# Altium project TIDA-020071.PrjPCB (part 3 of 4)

## Sheet Connector.SchDoc
size A3; Date: Not shown in title block; ApprovedBy: Not shown in title block; CheckedBy: Not shown in title block; Author: Not shown in title block; CompanyName: Not shown in title block; Engineer: Not shown in title block; Organization: Not shown in title block; Address1: Not shown in title block; Address2: Not shown in title block; Address3: Not shown in title block; Address4: Not shown in title block; DocumentNumber: 1; Revision: Use project parameter SCH_Rev; SheetNumber: 1; SheetTotal: 15; PageSetup: Record=PageOptions¦CenterHorizontal=True¦CenterVertical=True¦PrintScale=1.00¦XCorrection=1.00¦YCorrection=1.00¦PrintKind=0¦BorderSize=5000000¦LeftOffset=0¦BottomOffset=0¦Orientation=2¦PaperLength=1000¦PaperWidth=1000¦Scale=100¦PaperSource=15¦PrintQuality=600¦MediaType=1¦DitherType=10¦PaperKind=Letter¦PrintScaleMode=1
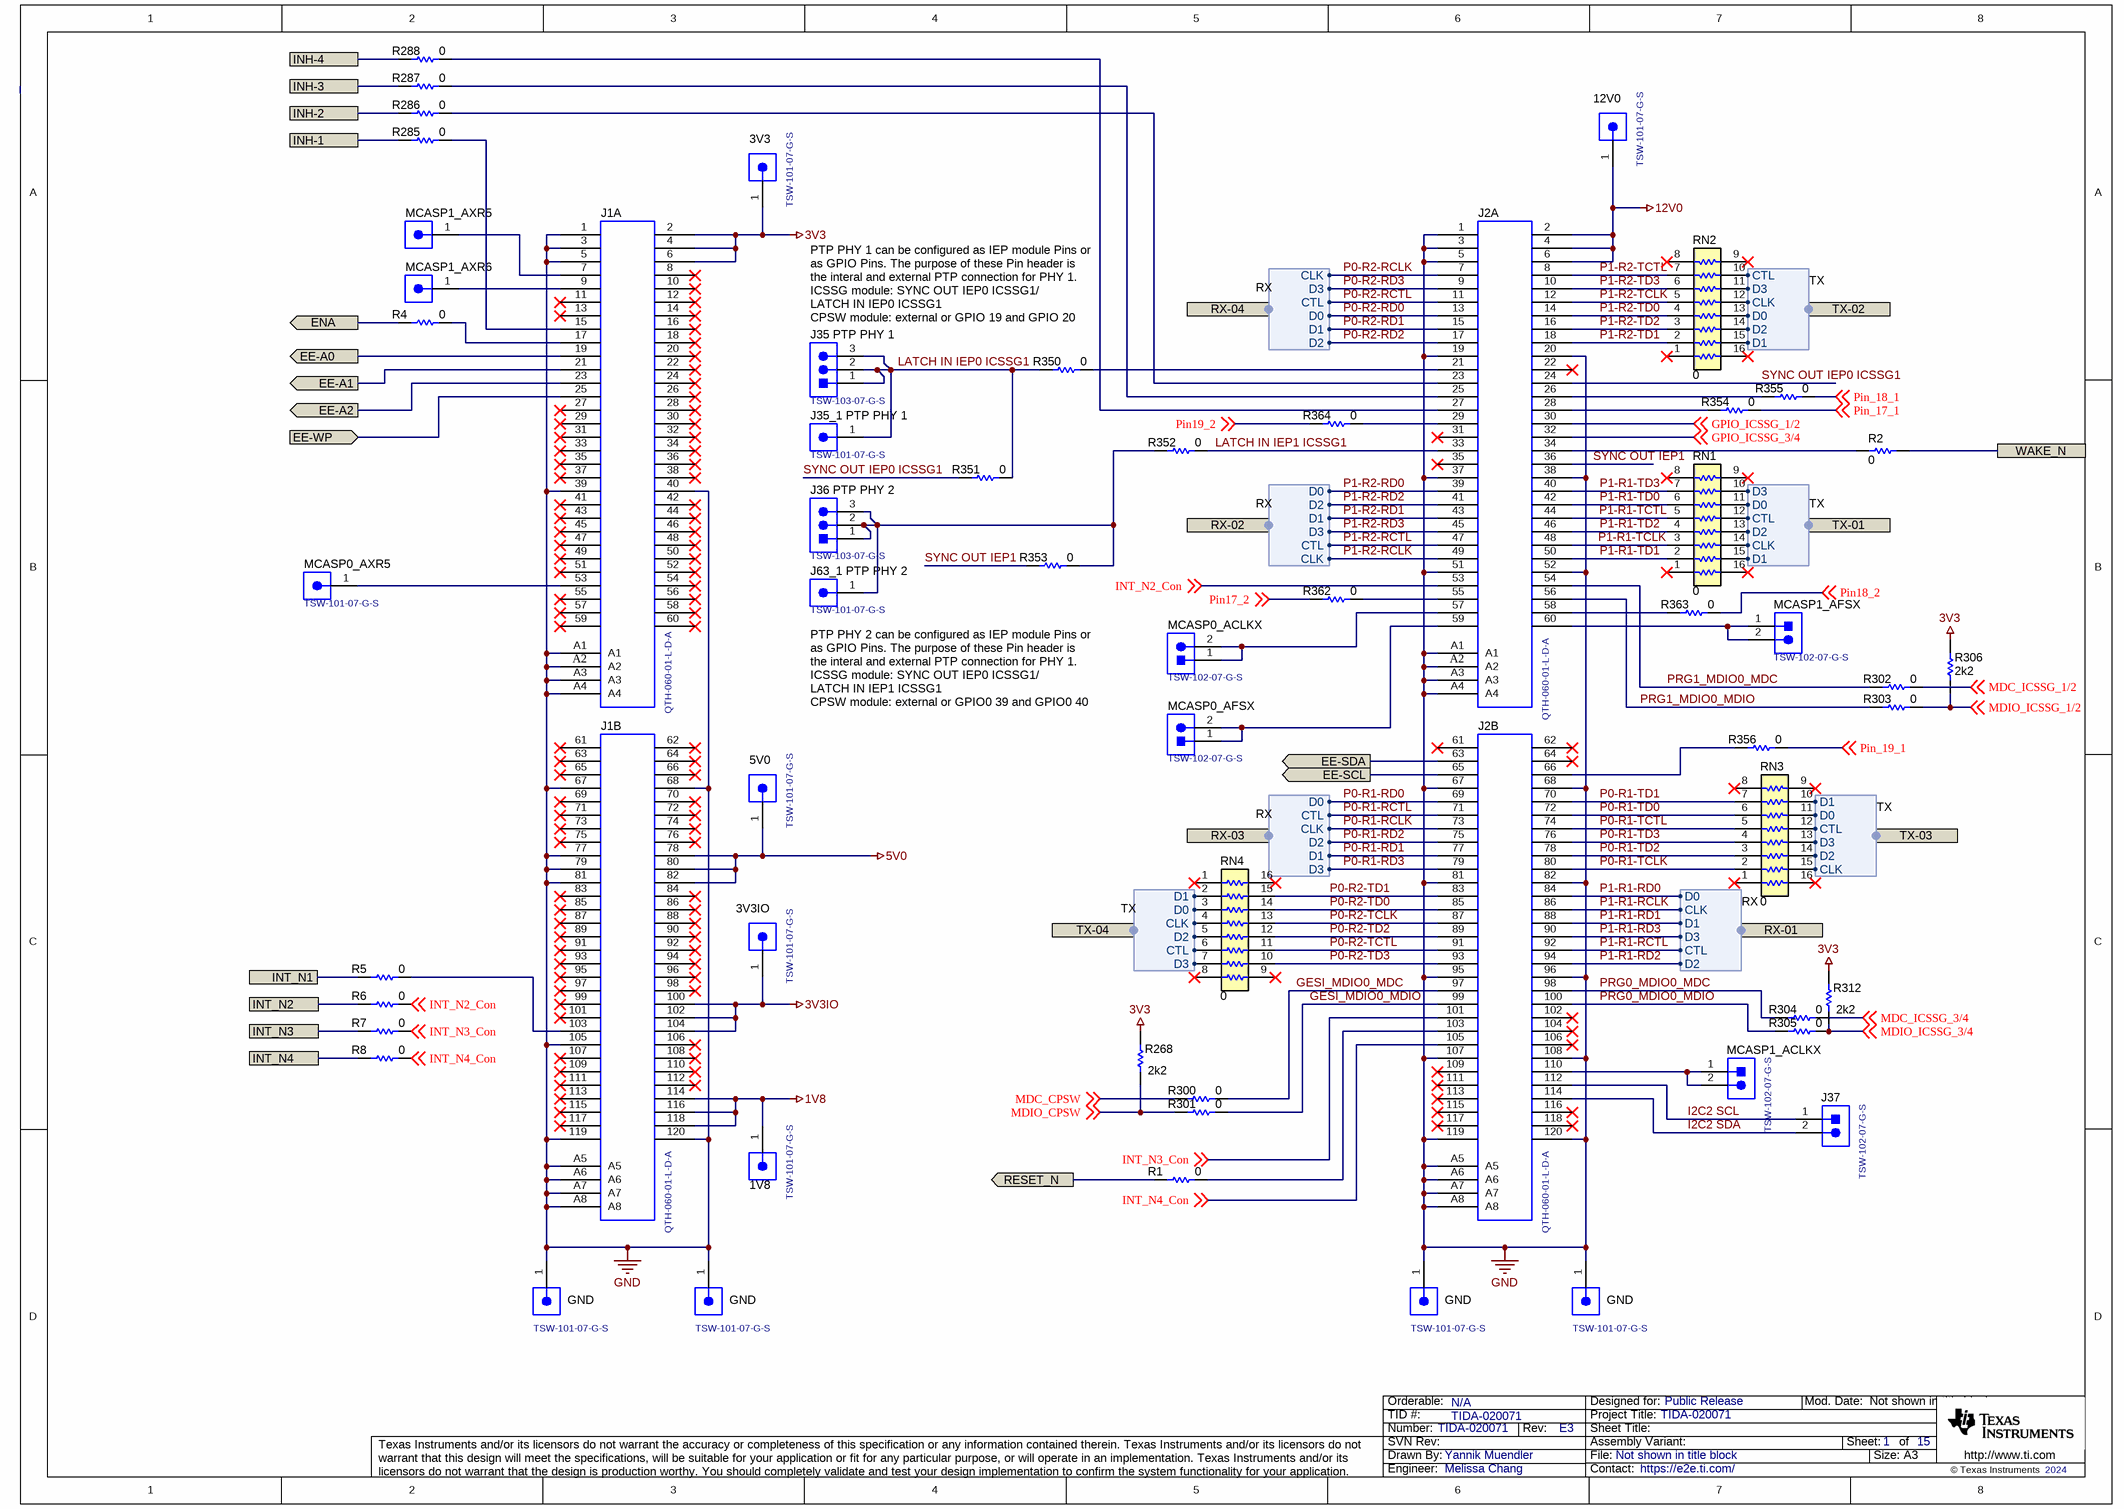
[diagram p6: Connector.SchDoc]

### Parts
(Parts that share a designator on the sheet are numbered #1, #2 ... from top to bottom, then left to right.)
1V8  TSW-101-07-G-S  [TSW-101-07-G-S]
3V3  TSW-101-07-G-S  [TSW-101-07-G-S]
3V3IO  TSW-101-07-G-S  [TSW-101-07-G-S]
5V0  TSW-101-07-G-S  [TSW-101-07-G-S]
12V0  TSW-101-07-G-S  [TSW-101-07-G-S]
GND#1  TSW-101-07-G-S  [TSW-101-07-G-S]
GND#2  TSW-101-07-G-S  [TSW-101-07-G-S]
GND#3  TSW-101-07-G-S  [TSW-101-07-G-S]
GND#4  TSW-101-07-G-S  [TSW-101-07-G-S]
J1  QTH-060-01-L-D-A  [SAMTEC_QTH-060-01-L-D-A]  (parts A,B of 2)
J2  QTH-060-01-L-D-A  [SAMTEC_QTH-060-01-L-D-A]  (parts A,B of 2)
J35_1_PTP_PHY_1  TSW-101-07-G-S  [TSW-101-07-G-S]
J35_PTP_PHY_1  TSW-103-07-G-S  [TSW-103-07-G-S]
J36_PTP_PHY_2  TSW-103-07-G-S  [TSW-103-07-G-S]
J37  TSW-102-07-G-S  [TSW-102-07-G-S]
J63_1_PTP_PHY_2  TSW-101-07-G-S  [TSW-101-07-G-S]
MCASP0_ACLKX  TSW-102-07-G-S  [TSW-102-07-G-S]
MCASP0_AFSX  TSW-102-07-G-S  [TSW-102-07-G-S]
MCASP0_AXR5  TSW-101-07-G-S  [TSW-101-07-G-S]
MCASP1_ACLKX  TSW-102-07-G-S  [TSW-102-07-G-S]
MCASP1_AFSX  TSW-102-07-G-S  [TSW-102-07-G-S]
MCASP1_AXR5  TSW-101-07-G-S  [TSW-101-07-G-S]  (value not drawn)
MCASP1_AXR6  TSW-101-07-G-S  [TSW-101-07-G-S]  (value not drawn)
R1  ValueDisplayed: 0  [0402]  (hidden comment: CRCW04020000Z0EDHP)
R2  ValueDisplayed: 0  [0402]  (hidden comment: CRCW04020000Z0EDHP)
R4  ValueDisplayed: 0  [0402]  (hidden comment: CRCW04020000Z0EDHP)
R5  ValueDisplayed: 0  [0402]  (hidden comment: CRCW04020000Z0EDHP)
R6  ValueDisplayed: 0  [0402]  (hidden comment: CRCW04020000Z0EDHP)
R7  ValueDisplayed: 0  [0402]  (hidden comment: CRCW04020000Z0EDHP)
R8  ValueDisplayed: 0  [0402]  (hidden comment: CRCW04020000Z0EDHP)
R268  ValueDisplayed: 2k2  [0402]  (hidden comment: CRCW04022K20JNED)
R285  ValueDisplayed: 0  [0402]  (hidden comment: CRCW04020000Z0EDHP)
R286  ValueDisplayed: 0  [0402]  (hidden comment: CRCW04020000Z0EDHP)
R287  ValueDisplayed: 0  [0402]  (hidden comment: CRCW04020000Z0EDHP)
R288  ValueDisplayed: 0  [0402]  (hidden comment: CRCW04020000Z0EDHP)
R300  ValueDisplayed: 0  [0402]  (hidden comment: CRCW04020000Z0EDHP)
R301  ValueDisplayed: 0  [0402]  (hidden comment: CRCW04020000Z0EDHP)
R302  ValueDisplayed: 0  [0402]  (hidden comment: CRCW04020000Z0EDHP)
R303  ValueDisplayed: 0  [0402]  (hidden comment: CRCW04020000Z0EDHP)
R304  ValueDisplayed: 0  [0402]  (hidden comment: CRCW04020000Z0EDHP)
R305  ValueDisplayed: 0  [0402]  (hidden comment: CRCW04020000Z0EDHP)
R306  ValueDisplayed: 2k2  [0402]  (hidden comment: CRCW04022K20JNED)
R312  ValueDisplayed: 2k2  [0402]  (hidden comment: CRCW04022K20JNED)
R350  ValueDisplayed: 0  [0402]  (hidden comment: CRCW04020000Z0EDHP)
R351  ValueDisplayed: 0  [0402]  (hidden comment: CRCW04020000Z0EDHP)
R352  ValueDisplayed: 0  [0402]  (hidden comment: CRCW04020000Z0EDHP)
R353  ValueDisplayed: 0  [0402]  (hidden comment: CRCW04020000Z0EDHP)
R354  ValueDisplayed: 0  [0402]  (hidden comment: CRCW04020000Z0EDHP)
R355  ValueDisplayed: 0  [0402]  (hidden comment: CRCW04020000Z0EDHP)
R356  ValueDisplayed: 0  [0402]  (hidden comment: CRCW04020000Z0EDHP)
R362  ValueDisplayed: 0  [0402]  (hidden comment: CRCW04020000Z0EDHP)
R363  ValueDisplayed: 0  [0402]  (hidden comment: CRCW04020000Z0EDHP)
R364  ValueDisplayed: 0  [0402]  (hidden comment: CRCW04020000Z0EDHP)
RN1  ValueDisplayed: 0  [RESCAXS_EXB-2HV]  (hidden comment: EXB-2HVR000V)
RN2  ValueDisplayed: 0  [RESCAXS_EXB-2HV]  (hidden comment: EXB-2HVR000V)
RN3  ValueDisplayed: 0  [RESCAXS_EXB-2HV]  (hidden comment: EXB-2HVR000V)
RN4  ValueDisplayed: 0  [RESCAXS_EXB-2HV]  (hidden comment: EXB-2HVR000V)

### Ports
EE-A0 (out), EE-A1 (out), EE-A2 (out), EE-SCL (out), EE-SDA (out), EE-WP (in), ENA (out), INH-1, INH-2, INH-3, INH-4, INT_N1, INT_N2, INT_N3, INT_N4, RESET_N (out), RX-01 (harness RX), RX-02 (harness RX), RX-03 (harness RX), RX-04 (harness RX), TX-01 (harness TX), TX-02 (harness TX), TX-03 (harness TX), TX-04 (harness TX), WAKE_N

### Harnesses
TX: D0, D1, D2, D3, CTL, CLK
RX: D0, D1, D2, D3, CTL, CLK

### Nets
1V8: 1V8.1 J1.114 J1.116 J1.118
3V3: 3V3.1 J1.2 J1.4 J1.6 R268.2 R306.1 R312.2
3V3IO: 3V3IO.1 J1.100 J1.102 J1.104
5V0: 5V0.1 J1.78 J1.80 J1.82
12V0: 12V0.1 J2.2 J2.4 J2.6
GND: GND#1.1 GND#2.1 GND#3.1 GND#4.1 J1.1 J1.3 J1.5 J1.39 J1.40 J1.67 J1.68 J1.77 J1.79 J1.81 J1.105 J1.119 J1.120 J1.A1 J1.A2 J1.A3 J1.A4 J1.A5 J1.A6 J1.A7 J1.A8 J2.1 J2.3 J2.5 J2.19 J2.20 J2.37 J2.38 J2.51 J2.52 J2.67 J2.68 J2.81 J2.82 J2.95 J2.96 J2.107 J2.108 J2.119 J2.120 J2.A1 J2.A2 J2.A3 J2.A4 J2.A5 J2.A6 J2.A7 J2.A8
EE-A0: J1.19 ; port EE-A0
EE-A1: J1.21 ; port EE-A1
EE-A2: J1.23 ; port EE-A2
EE-SCL: J2.65 ; port EE-SCL
EE-SDA: J2.63 ; port EE-SDA
EE-WP: J1.25 ; port EE-WP
ENA: R4.2 ; port ENA
GESI_MDIO0_MDC: J2.97 R300.1
GESI_MDIO0_MDIO: J2.99 R301.1
GPIO_ICSSG_1/2: J2.30 ; off-sheet GPIO_ICSSG_1/2
GPIO_ICSSG_3/4: J2.32 ; off-sheet GPIO_ICSSG_3/4
I2C2 SCL: J2.112 J37.1
I2C2 SDA: J2.114 J37.2
INH-1: R285.2 ; port INH-1
INH-2: R286.2 ; port INH-2
INH-3: R287.2 ; port INH-3
INH-4: R288.2 ; port INH-4
INT_N1: R5.2 ; port INT_N1
INT_N2: R6.2 ; port INT_N2
INT_N2_Con: J2.53 R6.1 ; off-sheet INT_N2_Con
INT_N3: R7.2 ; port INT_N3
INT_N3_Con: J2.101 R7.1 ; off-sheet INT_N3_Con
INT_N4: R8.2 ; port INT_N4
INT_N4_Con: J2.105 R8.1 ; off-sheet INT_N4_Con
LATCH IN IEP0 ICSSG1: J35_1_PTP_PHY_1.1 J35_PTP_PHY_1.1 J35_PTP_PHY_1.2 J35_PTP_PHY_1.3 R350.2 R351.1
LATCH IN IEP1 ICSSG1: J2.33 R352.1
MDC_CPSW: R300.2 ; off-sheet MDC_CPSW
MDC_ICSSG_1/2: R302.1 ; off-sheet MDC_ICSSG_1/2
MDC_ICSSG_3/4: R304.1 ; off-sheet MDC_ICSSG_3/4
MDIO_CPSW: R268.1 R301.2 ; off-sheet MDIO_CPSW
MDIO_ICSSG_1/2: R303.1 R306.2 ; off-sheet MDIO_ICSSG_1/2
MDIO_ICSSG_3/4: R305.1 R312.1 ; off-sheet MDIO_ICSSG_3/4
P0-R1-RCLK: J2.73 ; port RX-03.CLK
P0-R1-RCTL: J2.71 ; port RX-03.CTL
P0-R1-RD0: J2.69 ; port RX-03.D0
P0-R1-RD1: J2.77 ; port RX-03.D1
P0-R1-RD2: J2.75 ; port RX-03.D2
P0-R1-RD3: J2.79 ; port RX-03.D3
P0-R1-TCLK: J2.80 RN3.2
P0-R1-TCTL: J2.74 RN3.5
P0-R1-TD0: J2.72 RN3.6
P0-R1-TD1: J2.70 RN3.7
P0-R1-TD2: J2.78 RN3.3
P0-R1-TD3: J2.76 RN3.4
P0-R2-RCLK: J2.7 ; port RX-04.CLK
P0-R2-RCTL: J2.11 ; port RX-04.CTL
P0-R2-RD0: J2.13 ; port RX-04.D0
P0-R2-RD1: J2.15 ; port RX-04.D1
P0-R2-RD2: J2.17 ; port RX-04.D2
P0-R2-RD3: J2.9 ; port RX-04.D3
P0-R2-TCLK: J2.87 RN4.13
P0-R2-TCTL: J2.91 RN4.11
P0-R2-TD0: J2.85 RN4.14
P0-R2-TD1: J2.83 RN4.15
P0-R2-TD2: J2.89 RN4.12
P0-R2-TD3: J2.93 RN4.10
P1-R1-RCLK: J2.86 ; port RX-01.CLK
P1-R1-RCTL: J2.92 ; port RX-01.CTL
P1-R1-RD0: J2.84 ; port RX-01.D0
P1-R1-RD1: J2.88 ; port RX-01.D1
P1-R1-RD2: J2.94 ; port RX-01.D2
P1-R1-RD3: J2.90 ; port RX-01.D3
P1-R1-TCLK: J2.48 RN1.3
P1-R1-TCTL: J2.44 RN1.5
P1-R1-TD0: J2.42 RN1.6
P1-R1-TD1: J2.50 RN1.2
P1-R1-TD2: J2.46 RN1.4
P1-R1-TD3: J2.40 RN1.7
P1-R2-RCLK: J2.49 ; port RX-02.CLK
P1-R2-RCTL: J2.47 ; port RX-02.CTL
P1-R2-RD0: J2.39 ; port RX-02.D0
P1-R2-RD1: J2.43 ; port RX-02.D1
P1-R2-RD2: J2.41 ; port RX-02.D2
P1-R2-RD3: J2.45 ; port RX-02.D3
P1-R2-TCLK: J2.12 RN2.5
P1-R2-TCTL: J2.8 RN2.7
P1-R2-TD0: J2.14 RN2.4
P1-R2-TD1: J2.18 RN2.2
P1-R2-TD2: J2.16 RN2.3
P1-R2-TD3: J2.10 RN2.6
Pin17_2: R362.2 ; off-sheet Pin17_2  [project net 721/725 Enable/2]
Pin18_2: R363.1 ; off-sheet Pin18_2
Pin19_2: R364.2 ; off-sheet Pin19_2
Pin_17_1: R354.1 ; off-sheet Pin_17_1  [project net 721/725 Enable/1]
Pin_18_1: R355.1 ; off-sheet Pin_18_1
Pin_19_1: R356.1 ; off-sheet Pin_19_1
PRG0_MDIO0_MDC: J2.98 R304.2
PRG0_MDIO0_MDIO: J2.100 R305.2
PRG1_MDIO0_MDC: J2.54 R302.2
PRG1_MDIO0_MDIO: J2.56 R303.2
RESET_N_ALL: R1.2 ; port RESET_N
SYNC OUT IEP0 ICSSG1: J2.24 R351.2
SYNC OUT IEP1: J2.36 R353.2
TX_CLK-1: RN1.14 ; port TX-01.CLK
TX_CLK-2: RN2.12 ; port TX-02.CLK
TX_CLK-3: RN3.15 ; port TX-03.CLK
TX_CLK-4: RN4.4 ; port TX-04.CLK
TX_CTRL-1: RN1.12 ; port TX-01.CTL
TX_CTRL-2: RN2.10 ; port TX-02.CTL
TX_CTRL-3: RN3.12 ; port TX-03.CTL
TX_CTRL-4: RN4.6 ; port TX-04.CTL
TX_D0-1: RN1.11 ; port TX-01.D0
TX_D0-2: RN2.13 ; port TX-02.D0
TX_D0-3: RN3.11 ; port TX-03.D0
TX_D0-4: RN4.3 ; port TX-04.D0
TX_D1-1: RN1.15 ; port TX-01.D1
TX_D1-2: RN2.15 ; port TX-02.D1
TX_D1-3: RN3.10 ; port TX-03.D1
TX_D1-4: RN4.2 ; port TX-04.D1
TX_D2-1: RN1.13 ; port TX-01.D2
TX_D2-2: RN2.14 ; port TX-02.D2
TX_D2-3: RN3.14 ; port TX-03.D2
TX_D2-4: RN4.5 ; port TX-04.D2
TX_D3-1: RN1.10 ; port TX-01.D3
TX_D3-2: RN2.11 ; port TX-02.D3
TX_D3-3: RN3.13 ; port TX-03.D3
TX_D3-4: RN4.7 ; port TX-04.D3
WAKE_N: R2.2 ; port WAKE_N
NetJ1_7: J1.7 MCASP1_AXR5.1
NetJ1_9: J1.9 MCASP1_AXR6.1
NetJ1_15: J1.15 R285.1
NetJ1_17: J1.17 R4.1
NetJ1_53: J1.53 MCASP0_AXR5.1
NetJ1_103: J1.103 R5.1
NetJ2_21: J2.21 R350.1
NetJ2_23: J2.23 R286.1
NetJ2_25: J2.25 R287.1
NetJ2_26: J2.26 R355.2
NetJ2_27: J2.27 R288.1
NetJ2_28: J2.28 R354.2
NetJ2_29: J2.29 R364.1
NetJ2_34: J2.34 R2.1
NetJ2_55: J2.55 R362.1
NetJ2_57: J2.57 MCASP0_ACLKX.1 MCASP0_ACLKX.2
NetJ2_58: J2.58 R363.2
NetJ2_59: J2.59 MCASP0_AFSX.1 MCASP0_AFSX.2
NetJ2_60: J2.60 MCASP1_AFSX.1 MCASP1_AFSX.2
NetJ2_66: J2.66 R356.2
NetJ2_103: J2.103 R1.1
NetJ2_110: J2.110 MCASP1_ACLKX.1 MCASP1_ACLKX.2
NetJ36_PTP_PHY_2_1: J36_PTP_PHY_2.1 J36_PTP_PHY_2.2 J36_PTP_PHY_2.3 J63_1_PTP_PHY_2.1 R352.2 R353.1

Not connected (* = marked no-connect by the designer): J1 8* 10* 11* 12* 13* 14* 16* 18* 20* 22* 24* 26* 27* 28* 29* 30* 31* 32* 33* 34* 35* 36* 37* 38* 41* 42* 43* 44* 45* 46* 47* 48* 49* 50* 51* 52* 54* 55* 56* 57* 58* 59* 60* 61* 62* 63* 64* 65* 66* 69* 70* 71* 72* 73* 74* 75* 76* 83* 84* 85* 86* 87* 88* 89* 90* 91* 92* 93* 94* 95* 96* 97* 98* 99* 101* 106* 107* 108* 109* 110* 111* 112* 113* 115* 117*; J2 22* 31* 35* 61* 62* 64* 102* 104* 106* 109* 111* 113* 115* 116* 117* 118*; RN1 1* 8* 9* 16*; RN2 1* 8* 9* 16*; RN3 1* 8* 9* 16*; RN4 1* 8* 9* 16*

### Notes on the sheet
- PTP PHY 1 can be configured as IEP module Pins or as GPIO Pins. The purpose of these Pin header is the interal and external PTP connection for PHY 1.
  ICSSG module: SYNC OUT IEP0 ICSSG1/
  LATCH IN IEP0 ICSSG1
  CPSW module: external or GPIO 19 and GPIO 20
- (near J63_1_PTP_PHY_2) PTP PHY 2 can be configured as IEP module Pins or as GPIO Pins. The purpose of these Pin header is the interal and external PTP connection for PHY 1.
  ICSSG module: SYNC OUT IEP0 ICSSG1/
  LATCH IN IEP1 ICSSG1
  CPSW module: external or GPIO0 39 and GPIO0 40

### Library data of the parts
1V8 3V3 3V3IO 5V0 12V0 GND#1-GND#4 J35_1_PTP_PHY_1 J63_1_PTP_PHY_2 MCASP0_AXR5 MCASP1_AXR5 MCASP1_AXR6 = CMP-0075403-1: Header, 100mil, 1pos, Gold, TH; Manufacturer: Samtec; Pitch_mm: 2.54; Cert_VDE: N; Gender: Male; Cert_CSA: Y; Voltage_V: 550V; Green_REACh: Passed; Current_A: 6.3A; CT: False; Green_Lifecycle: Active; Row_Count: 1; CNHeader: True
J1 J2 = CMP-0056023-2: Socket, 0.5MM, 60x2, Gold, SMT; Manufacturer: Samtec; Green_Lifecycle: Not Set; Green_REACh: Incomplete
J35_PTP_PHY_1 J36_PTP_PHY_2 = CMP-0075407-2: Header, 100mil, 3x1, Gold, TH; Manufacturer: Samtec; Pitch_mm: 2.54; Cert_VDE: N; Gender: Male; Cert_CSA: Y; Voltage_V: 550V; Green_REACh: Passed; Current_A: 6.3A; Green_Lifecycle: Active; Row_Count: 1
J37 MCASP0_ACLKX MCASP0_AFSX MCASP1_ACLKX MCASP1_AFSX = CMP-0075405-3: Header, 100mil, 2x1, Gold, TH; Manufacturer: Samtec; Pitch_mm: 2.54; Cert_VDE: N; Gender: Male; Cert_CSA: Y; Voltage_V: 550V; Green_REACh: Passed; Current_A: 6.3A; Green_Lifecycle: Active; Row_Count: 1
R1 R2 R4-R8 R285-R288 R300-R305 R350-R356 R362-R364 = CMP-0081856-1: RES, 0, 0%, 0.2 W, AEC-Q200 Grade 0, 0402; Manufacturer: Vishay-Dale; SizeAreaWB_mm2: 3; SizeArea_mm2: 0.5; AEC Qualified: Y; AEC Category: Q200; Value: 0; SizeZ_mm: 0.6; Power_W: 200mW; VDC_V: 50V; Value2: 0.2W; SizeX_mm: 1
R268 R306 R312 = CMP-0026890-5: RES, 2.2 k, 5%, 0.063 W, AEC-Q200 Grade 0, 0402; Manufacturer: Vishay-Dale; Power_W: 63mW; TempCo: 200 ppm/C; Value_Code: 2k20; Value: 2.2k; EIA_Code: E24; SizeX_mm: 1; SizeY_mm: 0.5; SizeZ_mm: 0.6; Value2: 0.063W; AEC Qualified: Y; VDC_V: 50V; AEC Category: Q200; AEC Grade: 0
RN1-RN4 = CMP-0015352-2: RES, 0, 5%, 0.0625 W, Resistor Array - 8x1; Manufacturer: Panasonic; Power_W: 62.5mW; TempCo: ppm/C; Value_Code: 0000; U/M: EA; Value: 0; EIA_Code: E24; AEC Category: Q200

## Sheet Conn-Rb-01.SchDoc
size A4; Date: Not shown in title block; ApprovedBy: Not shown in title block; CheckedBy: Not shown in title block; Author: Not shown in title block; CompanyName: Not shown in title block; Engineer: Not shown in title block; Organization: Not shown in title block; Address1: Not shown in title block; Address2: Not shown in title block; Address3: Not shown in title block; Address4: Not shown in title block; DocumentNumber: 6; Revision: Use project parameter SCH_Rev; SheetNumber: 6; SheetTotal: 15; PageSetup: Record=PageOptions¦CenterHorizontal=True¦CenterVertical=True¦PrintScale=1.00¦XCorrection=1.00¦YCorrection=1.00¦PrintKind=0¦BorderSize=5000000¦LeftOffset=0¦BottomOffset=0¦Orientation=2¦PaperLength=1000¦PaperWidth=1000¦Scale=100¦PaperSource=15¦PrintQuality=600¦MediaType=1¦DitherType=10¦PaperKind=Letter¦PrintScaleMode=1
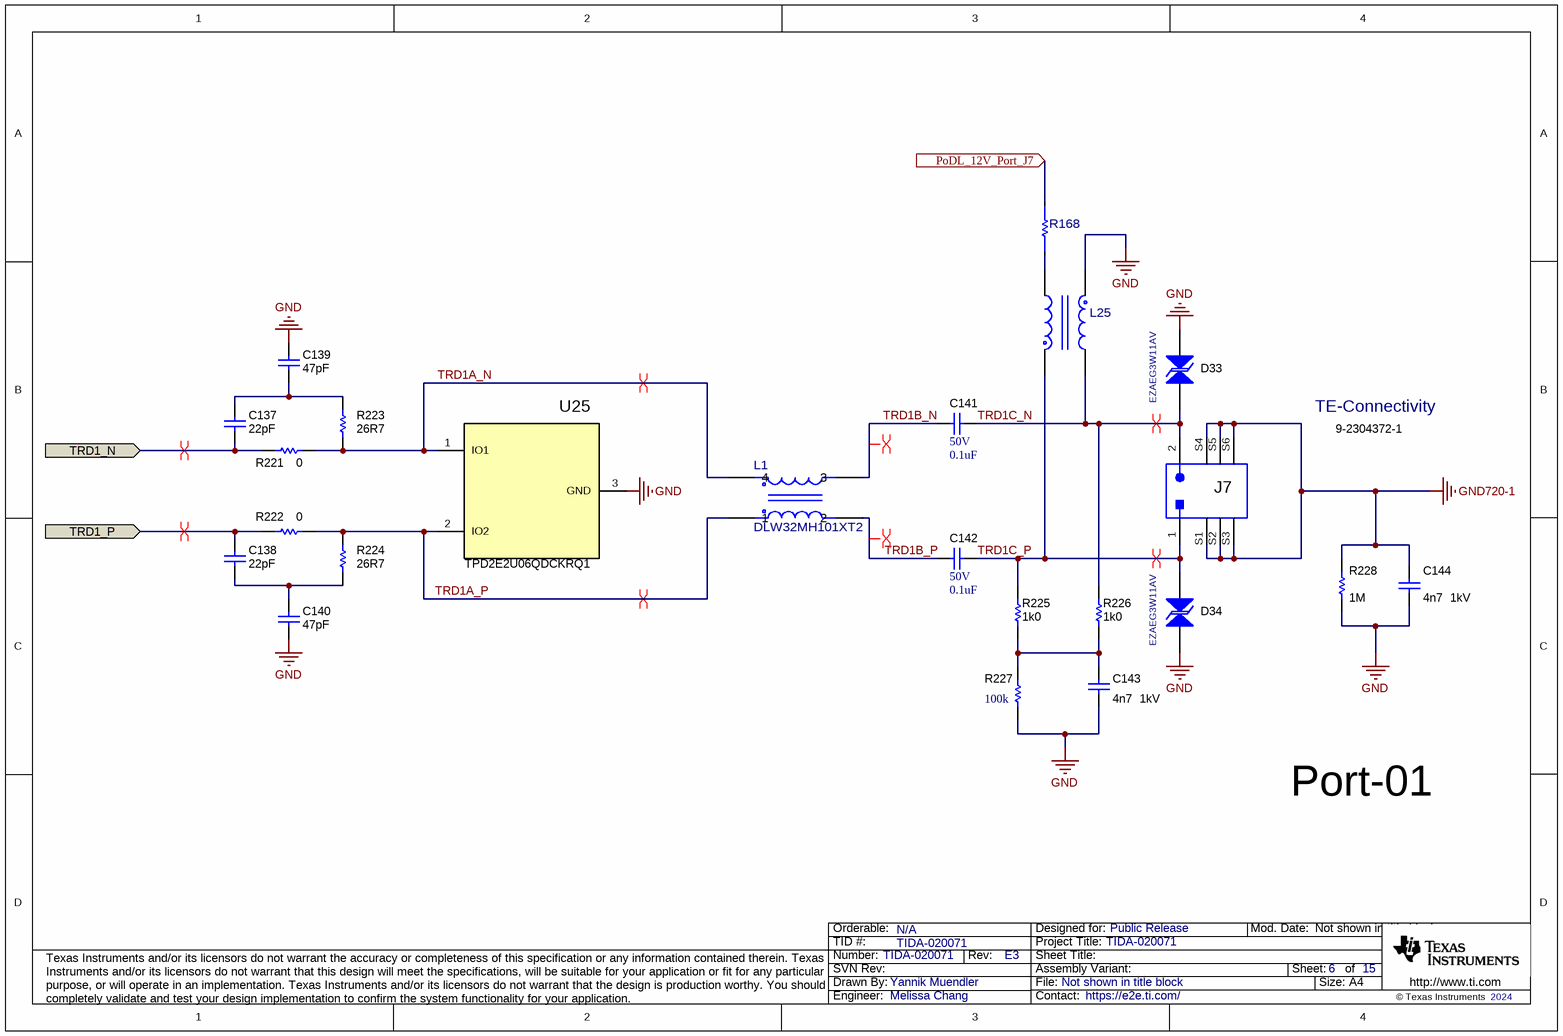
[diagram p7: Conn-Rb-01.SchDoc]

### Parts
C137  ValueDisplayed: 22pF  [0402]  (hidden comment: GRM1555C1H220FA01D)
C138  ValueDisplayed: 22pF  [0402]  (hidden comment: GRM1555C1H220FA01D)
C139  ValueDisplayed: 47pF  [0402]  (hidden comment: GRM1555C1H470FA01D)
C140  ValueDisplayed: 47pF  [0402]  (hidden comment: GRM1555C1H470FA01D)
C141  VDC_V: 50V  ValueDisplayed: 0.1uF  [0402]  (hidden comment: GCM155R71H104KE02D)
C142  VDC_V: 50V  ValueDisplayed: 0.1uF  [0402]  (hidden comment: GCM155R71H104KE02D)
C143  VDC_V: 1kV  ValueDisplayed: 4n7  [1206]  (hidden comment: GRM31BR73A472KW01L)
C144  VDC_V: 1kV  ValueDisplayed: 4n7  [1206]  (hidden comment: GRM31BR73A472KW01L)
D33  EZAEG3W11AV  [0603]
D34  EZAEG3W11AV  [0603]
J7  9-2304372-1  Supplier 1: TE-Connectivity  [TE_1PORT_B1-B]
L1  DLW32MH101XT2  [FP-DLW32MH101XT2_1210-MFG]
L25  ADL32VHR-3R9M  [FP-ADL32VHR-3R9M_SMT_3MM2_2MM5-MFG]  (value not drawn)
R168  RMCF0805ZT0R00  [FP-RMCF0805ZT0R00_0805-MFG]  (value not drawn)
R221  ValueDisplayed: 0  [0402]  (hidden comment: CRCW04020000Z0EDHP)
R222  ValueDisplayed: 0  [0402]  (hidden comment: CRCW04020000Z0EDHP)
R223  ValueDisplayed: 26R7  [0402]  (hidden comment: CRCW040226R7FKED)
R224  ValueDisplayed: 26R7  [0402]  (hidden comment: CRCW040226R7FKED)
R225  ValueDisplayed: 1k0  [0805_HV]  (hidden comment: ERJ-P06F1001V)
R226  ValueDisplayed: 1k0  [0805_HV]  (hidden comment: ERJ-P06F1001V)
R227  ValueDisplayed: 100k  [0805_HV]  (hidden comment: CRCW0805100KFKEA)
R228  ValueDisplayed: 1M  [1206]  (hidden comment: CRCW12061M00JNEA)
U25  TPD2E2U06QDCKRQ1  [DCK0003A_N]

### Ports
PoDL_12V_Port_J7 (in), TRD1_N (in), TRD1_P (in)

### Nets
GND: C139.1 C140.2 C143.2 C144.2 D33.2 D34.1 L25.3 R227.1 R228.2 U25.3(GND)
GND720-1: C144.1 J7.S1(GND) J7.S2(GND) J7.S3(GND) J7.S4(GND) J7.S5(GND) J7.S6(GND) R228.1
PoDL_12V_Port_J7: R168.2 ; port PoDL_12V_Port_J7
TRD1_N: C137.2 R221.2 ; port TRD1_N
TRD1_P: C138.1 R222.2 ; port TRD1_P
TRD1A_N: L1.4 R221.1 R223.1 U25.1(IO1)
TRD1A_P: L1.1 R222.1 R224.2 U25.2(IO2)
TRD1B_N: C141.2 L1.3
TRD1B_P: C142.2 L1.2
TRD1C_N: C141.1 D33.1 J7.2 L25.4 R226.2
TRD1C_P: C142.1 D34.2 J7.1 L25.1 R225.2
NetC137_1: C137.1 C139.2 R223.2
NetC138_2: C138.2 C140.1 R224.1
NetC143_1: C143.1 R225.1 R226.1 R227.2
NetL25_2: L25.2 R168.1

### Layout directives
differential pair: TRD1_N, TRD1_P, TRD1A_N, TRD1A_P, TRD1B_N, TRD1B_P, TRD1C_N, TRD1C_P

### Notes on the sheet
- Port-01

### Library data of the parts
C137 C138 = CMP-0006438-2: CAP, CERM, 22 pF, 50 V, +/- 1%, C0G/NP0, 0402; Manufacturer: MuRata; TaMin_C: -55°C; Polarized: N; SizeAreaWB_mm2: 3; Value1: Unknown; U/M: EA; Value: 22pF; TaMax_C: 125°C; SizeZ_mm: 0.6; SizeX_mm: 1; SizeY_mm: 0.5; Value2: 50V; AEC Category: Q200
C139 C140 = CMP-0006467-2: CAP, CERM, 47 pF, 50 V, +/- 1%, C0G/NP0, 0402; Manufacturer: MuRata; TaMin_C: -55°C; Polarized: N; SizeAreaWB_mm2: 3; Value1: Unknown; U/M: EA; Value: 47pF; TaMax_C: 125°C; SizeZ_mm: 0.6; SizeX_mm: 1; SizeY_mm: 0.5; Value2: 50V; AEC Category: Q200
C141 C142 = CMP-0006356-2: CAP, CERM, 0.1 uF, 50 V, +/- 10%, X7R, AEC-Q200 Grade 1, 0402; Manufacturer: MuRata; TaMin_C: -55°C; Polarized: N; SizeAreaWB_mm2: 3; Value1: Unknown; U/M: EA; Value: 0.1uF; TaMax_C: 125°C; SizeZ_mm: 0.6; SizeX_mm: 1; SizeY_mm: 0.5; AEC Qualified: Y; Cap_F: 100nF; AEC Category: Q200
C143 C144 = CMP-0008920-2: CAP, CERM, 4700 pF, 1000 V, +/- 10%, X7R, 1206; Manufacturer: MuRata; TaMin_C: -55°C; Polarized: N; SizeAreaWB_mm2: 10.92; Value1: Unknown; U/M: EA; Value: 4700pF; TaMax_C: 125°C; SizeZ_mm: 1.35; SizeX_mm: 3.2; SizeY_mm: 1.6; Value2: 1000V; SizeArea_mm2: 5.12; Cap_F: 4.7nF; AEC Category: Q200
D33 D34 = CMP-0086344-1: Diode, TVS, Bi, AEC-Q101, 0603; Manufacturer: Panasonic; SizeX_mm: 1.6; AEC Qualified: Y; SizeArea_mm2: 1.28; SizeY_mm: 0.8; SizeAreaWB_mm2: 4.68; AEC Category: Q101; SizeZ_mm: 1
J7 = CMP-0054903-1: Header(shrouded), 2x1, R/A, TH; Manufacturer: TE Connectivity; Gender: Male; Pitch_mm: 1.8; CT: FALSE; Row_Count: 1; Shrouded: Y
L1 = CMP-0090833-1: 100μH @ 100kHz 2 Line Common Mode Choke Surface Mount 100mA DCR 3.12Ω; Manufacturer: Murata; AEC Qualified: Yes; SizeZ_mm: 2.5mm; DCR_ohm: 3.12; AEC Grade: Grade 1; Tolerance_%: -25/+50%
L25 = CMP-0098175-1: Differential Mode Choke 3.9uH 540mA 0.36Ohm 3.2x2.5x2.5mm SMT; Manufacturer: TDK; Ind_H: 3.9µH; Isat: 860mA; DCR_ohm: 0.36; Tolerance_%: 20%; SizeZ_mm: 2.5mm; Test Frequency: 100kHz; AEC Qualified: No
R168 = CMP-0089632-1: 0 Ohms Jumper 0.125W, 1/8W Chip Resistor 0805 (2012 Metric) Automotive AEC-Q200 Thick Film; Manufacturer: Stackpole Electronics; TempCo: 200ppm/°C; SizeZ_mm: 0.65mm; AEC Grade: Grade 0; AEC Qualified: Yes; Res_ohm: 0; Power_W: 125mW; VDC_V: 150V
R221 R222 = CMP-0081856-1: as R1 on sheet Connector
R223 R224 = CMP-0026210-2: RES, 26.7, 1%, 0.063 W, AEC-Q200 Grade 0, 0402; Manufacturer: Vishay-Dale; Power_W: 63mW; TempCo: 100 ppm/C; Value: 26.7; SizeX_mm: 1; SizeY_mm: 0.5; SizeZ_mm: 0.6; Value2: 0.063W; AEC Qualified: Y; VDC_V: 50V; AEC Grade: 0; AEC Category: Q200; EIA_Code: E96
R225 R226 = CMP-0021848-2: RES, 1.00 k, 1%, 0.25 W, 0805; Manufacturer: Panasonic; Power_W: 250mW; TempCo: 100 ppm/C; Value_Code: 1k00; U/M: EA; Value: 1.00k; EIA_Code: E96; Res_ohm: 1k; SizeX_mm: 2; SizeY_mm: 1.25; SizeZ_mm: 1.45; Value2: 0.25W; SizeArea_mm2: 2.5; VDC_V: 400V; AEC Category: Q200
R227 = CMP-0020834-3: RES, 100 k, 1%, 0.125 W, AEC-Q200 Grade 0, 0805; Manufacturer: Vishay-Dale; Power_W: 125mW; TempCo: 100 ppm/C; Value: 100k; EIA_Code: E96; SizeX_mm: 2; SizeY_mm: 1.25; SizeZ_mm: 1.45; Value2: 0.125W; SizeArea_mm2: 2.5; AEC Qualified: Y; AEC Category: Q200; AEC Grade: 0; VDC_V: 150V
R228 = CMP-0018610-3: RES, 1.0 M, 5%, 0.25 W, AEC-Q200 Grade 0, 1206; Manufacturer: Vishay-Dale; Power_W: 250mW; TempCo: 200 ppm/C; Value_Code: 1M00; Value: 1.0Meg; EIA_Code: E24; SizeX_mm: 3.2; SizeY_mm: 1.6; SizeZ_mm: 1.35; Value2: 0.25W; SizeArea_mm2: 5.12; AEC Qualified: Y; VDC_V: 200V; AEC Category: Q200; AEC Grade: 0
U25 = CMP-0073595-1: Automotive Dual-Channel High-Speed ESD Protection Device, DCK0003A (SOT-SC70-3); Alternate Manufacturer: Texas Instruments; SizeAreaWB_mm2: 9.3; U/M: EA; SizeZ_mm: 1.1; SizeX_mm: 2.1; SizeY_mm: 2.0; SizeArea_mm2: 4.2; CompType: IC

## Sheet Conn-Rb-02.SchDoc
size A4; Date: Not shown in title block; ApprovedBy: Not shown in title block; CheckedBy: Not shown in title block; Author: Not shown in title block; CompanyName: Not shown in title block; Engineer: Not shown in title block; Organization: Not shown in title block; Address1: Not shown in title block; Address2: Not shown in title block; Address3: Not shown in title block; Address4: Not shown in title block; DocumentNumber: 7; Revision: Use project parameter SCH_Rev; SheetNumber: 7; SheetTotal: 15; PageSetup: Record=PageOptions¦CenterHorizontal=True¦CenterVertical=True¦PrintScale=1.00¦XCorrection=1.00¦YCorrection=1.00¦PrintKind=0¦BorderSize=5000000¦LeftOffset=0¦BottomOffset=0¦Orientation=2¦PaperLength=1000¦PaperWidth=1000¦Scale=100¦PaperSource=15¦PrintQuality=600¦MediaType=1¦DitherType=10¦PaperKind=Letter¦PrintScaleMode=1
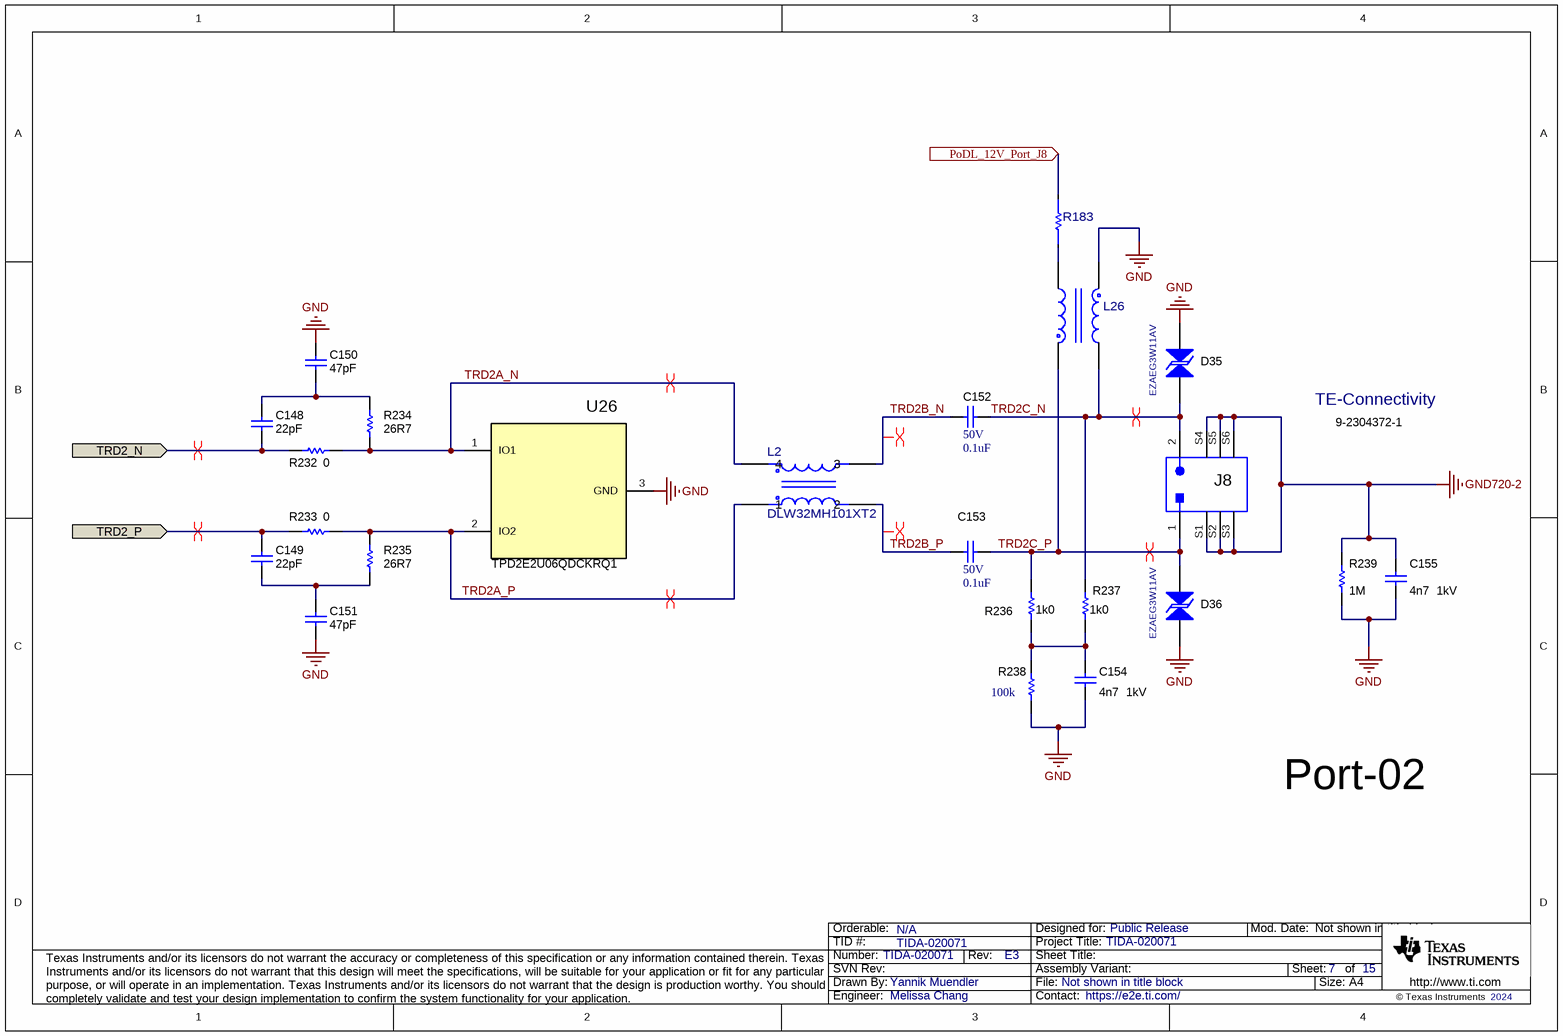
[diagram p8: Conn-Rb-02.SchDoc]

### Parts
C148  ValueDisplayed: 22pF  [0402]  (hidden comment: GRM1555C1H220FA01D)
C149  ValueDisplayed: 22pF  [0402]  (hidden comment: GRM1555C1H220FA01D)
C150  ValueDisplayed: 47pF  [0402]  (hidden comment: GRM1555C1H470FA01D)
C151  ValueDisplayed: 47pF  [0402]  (hidden comment: GRM1555C1H470FA01D)
C152  VDC_V: 50V  ValueDisplayed: 0.1uF  [0402]  (hidden comment: GCM155R71H104KE02D)
C153  VDC_V: 50V  ValueDisplayed: 0.1uF  [0402]  (hidden comment: GCM155R71H104KE02D)
C154  VDC_V: 1kV  ValueDisplayed: 4n7  [1206]  (hidden comment: GRM31BR73A472KW01L)
C155  VDC_V: 1kV  ValueDisplayed: 4n7  [1206]  (hidden comment: GRM31BR73A472KW01L)
D35  EZAEG3W11AV  [0603]
D36  EZAEG3W11AV  [0603]
J8  9-2304372-1  Supplier 1: TE-Connectivity  [TE_1PORT_B1-B]
L2  DLW32MH101XT2  [FP-DLW32MH101XT2_1210-MFG]
L26  ADL32VHR-3R9M  [FP-ADL32VHR-3R9M_SMT_3MM2_2MM5-MFG]  (value not drawn)
R183  RMCF0805ZT0R00  [FP-RMCF0805ZT0R00_0805-MFG]  (value not drawn)
R232  ValueDisplayed: 0  [0402]  (hidden comment: CRCW04020000Z0EDHP)
R233  ValueDisplayed: 0  [0402]  (hidden comment: CRCW04020000Z0EDHP)
R234  ValueDisplayed: 26R7  [0402]  (hidden comment: CRCW040226R7FKED)
R235  ValueDisplayed: 26R7  [0402]  (hidden comment: CRCW040226R7FKED)
R236  ValueDisplayed: 1k0  [0805_HV]  (hidden comment: ERJ-P06F1001V)
R237  ValueDisplayed: 1k0  [0805_HV]  (hidden comment: ERJ-P06F1001V)
R238  ValueDisplayed: 100k  [0805_HV]  (hidden comment: CRCW0805100KFKEA)
R239  ValueDisplayed: 1M  [1206]  (hidden comment: CRCW12061M00JNEA)
U26  TPD2E2U06QDCKRQ1  [DCK0003A_N]

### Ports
PoDL_12V_Port_J8 (in), TRD2_N (in), TRD2_P (in)

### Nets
GND: C150.1 C151.2 C154.2 C155.1 D35.2 D36.1 L26.3 R238.1 R239.2 U26.3(GND)
GND720-2: C155.2 J8.S1(GND) J8.S2(GND) J8.S3(GND) J8.S4(GND) J8.S5(GND) J8.S6(GND) R239.1
PoDL_12V_Port_J8: R183.2 ; port PoDL_12V_Port_J8
TRD2_N: C148.2 R232.2 ; port TRD2_N
TRD2_P: C149.1 R233.2 ; port TRD2_P
TRD2A_N: L2.4 R232.1 R234.1 U26.1(IO1)
TRD2A_P: L2.1 R233.1 R235.2 U26.2(IO2)
TRD2B_N: C152.2 L2.3
TRD2B_P: C153.2 L2.2
TRD2C_N: C152.1 D35.1 J8.2 L26.4 R237.2
TRD2C_P: C153.1 D36.2 J8.1 L26.1 R236.2
NetC148_1: C148.1 C150.2 R234.2
NetC149_2: C149.2 C151.1 R235.1
NetC154_1: C154.1 R236.1 R237.1 R238.2
NetL26_2: L26.2 R183.1

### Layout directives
differential pair: TRD2_N, TRD2_P, TRD2A_N, TRD2A_P, TRD2B_N, TRD2B_P, TRD2C_N, TRD2C_P

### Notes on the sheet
- Port-02

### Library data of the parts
C148 C149 = CMP-0006438-2: as C137 on sheet Conn-Rb-01
C150 C151 = CMP-0006467-2: as C139 on sheet Conn-Rb-01
C152 C153 = CMP-0006356-2: as C141 on sheet Conn-Rb-01
C154 C155 = CMP-0008920-2: as C143 on sheet Conn-Rb-01
D35 D36 = CMP-0086344-1: as D33 on sheet Conn-Rb-01
J8 = CMP-0054903-1: as J7 on sheet Conn-Rb-01
L2 = CMP-0090833-1: as L1 on sheet Conn-Rb-01
L26 = CMP-0098175-1: as L25 on sheet Conn-Rb-01
R183 = CMP-0089632-1: as R168 on sheet Conn-Rb-01
R232 R233 = CMP-0081856-1: as R1 on sheet Connector
R234 R235 = CMP-0026210-2: as R223 on sheet Conn-Rb-01
R236 R237 = CMP-0021848-2: as R225 on sheet Conn-Rb-01
R238 = CMP-0020834-3: as R227 on sheet Conn-Rb-01
R239 = CMP-0018610-3: as R228 on sheet Conn-Rb-01
U26 = CMP-0073595-1: as U25 on sheet Conn-Rb-01

## Sheet Conn-TE-01.SchDoc
size A4; Date: Not shown in title block; ApprovedBy: Not shown in title block; CheckedBy: Not shown in title block; Author: Not shown in title block; CompanyName: Not shown in title block; Engineer: Not shown in title block; Organization: Not shown in title block; Address1: Not shown in title block; Address2: Not shown in title block; Address3: Not shown in title block; Address4: Not shown in title block; DocumentNumber: 8; Revision: Use project parameter SCH_Rev; SheetNumber: 8; SheetTotal: 15; PageSetup: Record=PageOptions¦CenterHorizontal=True¦CenterVertical=True¦PrintScale=1.00¦XCorrection=1.00¦YCorrection=1.00¦PrintKind=0¦BorderSize=5000000¦LeftOffset=0¦BottomOffset=0¦Orientation=2¦PaperLength=1000¦PaperWidth=1000¦Scale=100¦PaperSource=15¦PrintQuality=600¦MediaType=1¦DitherType=10¦PaperKind=Letter¦PrintScaleMode=1
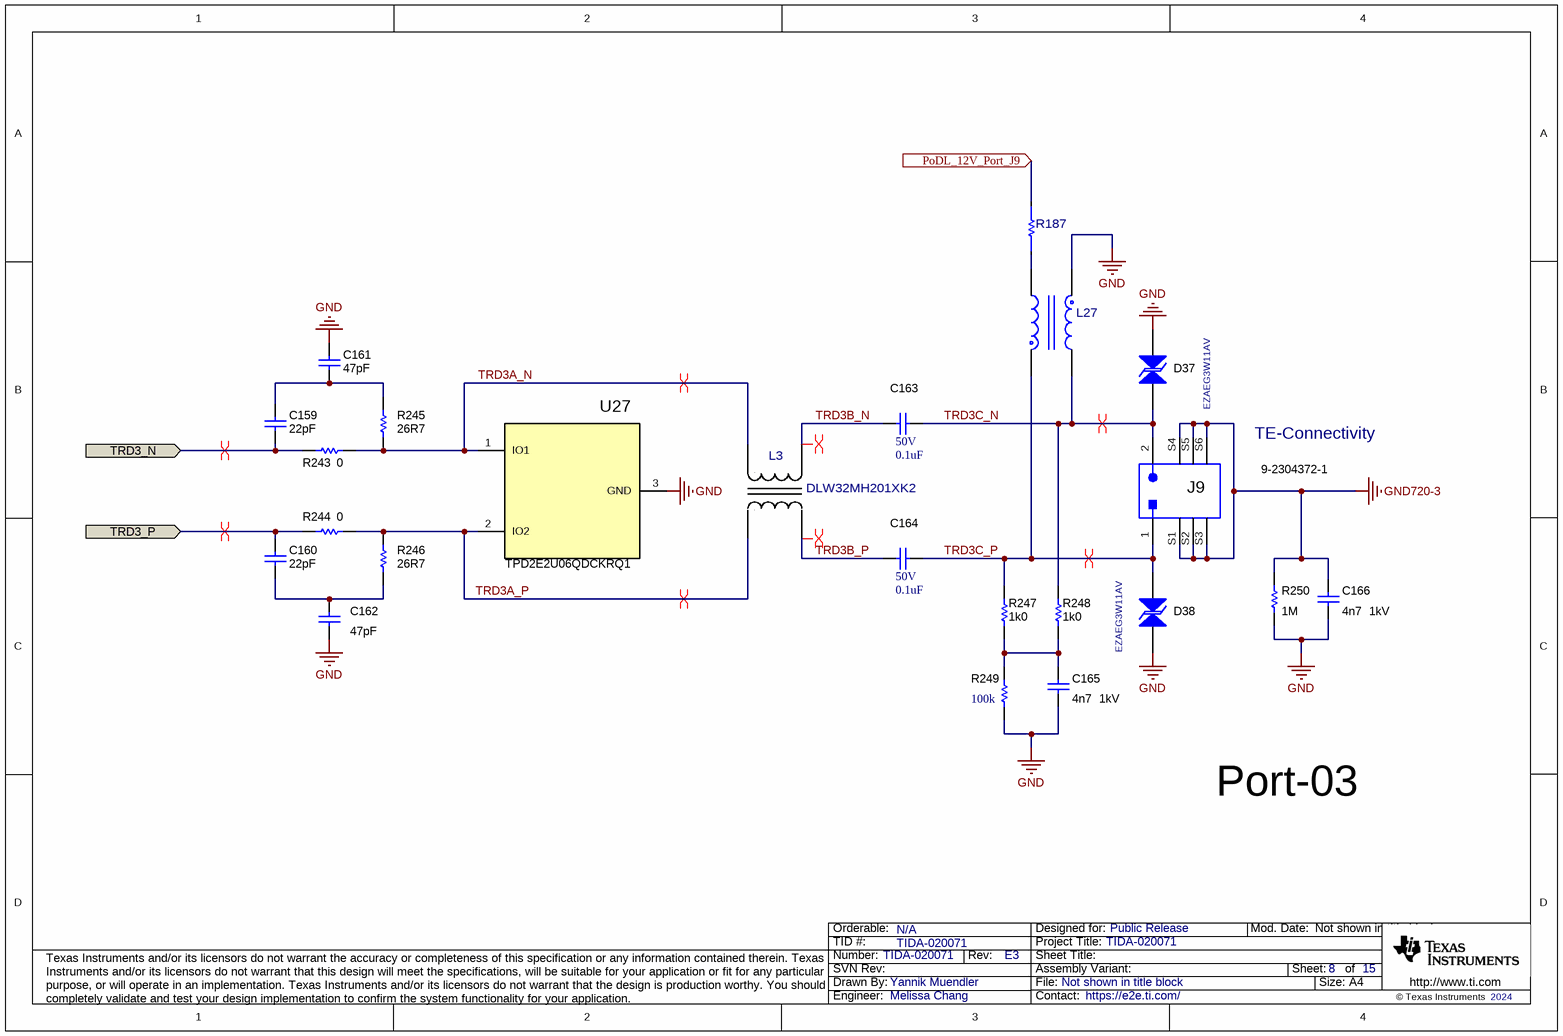
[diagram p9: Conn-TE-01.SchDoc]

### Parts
C159  ValueDisplayed: 22pF  [0402]  (hidden comment: GRM1555C1H220FA01D)
C160  ValueDisplayed: 22pF  [0402]  (hidden comment: GRM1555C1H220FA01D)
C161  ValueDisplayed: 47pF  [0402]  (hidden comment: GRM1555C1H470FA01D)
C162  ValueDisplayed: 47pF  [0402]  (hidden comment: GRM1555C1H470FA01D)
C163  VDC_V: 50V  ValueDisplayed: 0.1uF  [0402]  (hidden comment: GCM155R71H104KE02D)
C164  VDC_V: 50V  ValueDisplayed: 0.1uF  [0402]  (hidden comment: GCM155R71H104KE02D)
C165  VDC_V: 1kV  ValueDisplayed: 4n7  [1206]  (hidden comment: GRM31BR73A472KW01L)
C166  VDC_V: 1kV  ValueDisplayed: 4n7  [1206]  (hidden comment: GRM31BR73A472KW01L)
D37  EZAEG3W11AV  [0603]
D38  EZAEG3W11AV  [0603]
J9  9-2304372-1  Supplier 1: TE-Connectivity  [TE_1PORT_B1-B]
L3  DLW32MH201XK2  [FP-DLW32MH201XK2_1210-MFG]
L27  ADL32VHR-3R9M  [FP-ADL32VHR-3R9M_SMT_3MM2_2MM5-MFG]  (value not drawn)
R187  RMCF0805ZT0R00  [FP-RMCF0805ZT0R00_0805-MFG]  (value not drawn)
R243  ValueDisplayed: 0  [0402]  (hidden comment: CRCW04020000Z0EDHP)
R244  ValueDisplayed: 0  [0402]  (hidden comment: CRCW04020000Z0EDHP)
R245  ValueDisplayed: 26R7  [0402]  (hidden comment: CRCW040226R7FKED)
R246  ValueDisplayed: 26R7  [0402]  (hidden comment: CRCW040226R7FKED)
R247  ValueDisplayed: 1k0  [0805_HV]  (hidden comment: ERJ-P06F1001V)
R248  ValueDisplayed: 1k0  [0805_HV]  (hidden comment: ERJ-P06F1001V)
R249  ValueDisplayed: 100k  [0805_HV]  (hidden comment: CRCW0805100KFKEA)
R250  ValueDisplayed: 1M  [1206]  (hidden comment: CRCW12061M00JNEA)
U27  TPD2E2U06QDCKRQ1  [DCK0003A_N]

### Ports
PoDL_12V_Port_J9 (in), TRD3_N (in), TRD3_P (in)

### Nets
GND: C161.1 C162.2 C165.2 C166.2 D37.2 D38.1 L27.3 R249.1 R250.2 U27.3(GND)
GND720-3: C166.1 J9.S1(GND) J9.S2(GND) J9.S3(GND) J9.S4(GND) J9.S5(GND) J9.S6(GND) R250.1
PoDL_12V_Port_J9: R187.2 ; port PoDL_12V_Port_J9
TRD3_N: C159.2 R243.2 ; port TRD3_N
TRD3_P: C160.1 R244.2 ; port TRD3_P
TRD3A_N: L3.4 R243.1 R245.1 U27.1(IO1)
TRD3A_P: L3.1 R244.1 R246.2 U27.2(IO2)
TRD3B_N: C163.2 L3.3
TRD3B_P: C164.2 L3.2
TRD3C_N: C163.1 D37.1 J9.2 L27.4 R248.2
TRD3C_P: C164.1 D38.2 J9.1 L27.1 R247.2
NetC159_1: C159.1 C161.2 R245.2
NetC160_2: C160.2 C162.1 R246.1
NetC165_1: C165.1 R247.1 R248.1 R249.2
NetL27_2: L27.2 R187.1

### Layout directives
differential pair: TRD3_N, TRD3_P, TRD3A_N, TRD3A_P, TRD3B_N, TRD3B_P, TRD3C_N, TRD3C_P

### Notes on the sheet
- Port-03

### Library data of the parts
C159 C160 = CMP-0006438-2: as C137 on sheet Conn-Rb-01
C161 C162 = CMP-0006467-2: as C139 on sheet Conn-Rb-01
C163 C164 = CMP-0006356-2: as C141 on sheet Conn-Rb-01
C165 C166 = CMP-0008920-2: as C143 on sheet Conn-Rb-01
D37 D38 = CMP-0086344-1: as D33 on sheet Conn-Rb-01
J9 = CMP-0054903-1: as J7 on sheet Conn-Rb-01
L3 = CMP-0087001-1: 200µH @ 100kHz 2 Line Common Mode Choke Surface Mount 70mA DCR 4.8 Ohm; Manufacturer: Murata; AEC Grade: Grade 1; AEC Qualified: Yes; SizeZ_mm: 2.5mm
L27 = CMP-0098175-1: as L25 on sheet Conn-Rb-01
R187 = CMP-0089632-1: as R168 on sheet Conn-Rb-01
R243 R244 = CMP-0081856-1: as R1 on sheet Connector
R245 R246 = CMP-0026210-2: as R223 on sheet Conn-Rb-01
R247 R248 = CMP-0021848-2: as R225 on sheet Conn-Rb-01
R249 = CMP-0020834-3: as R227 on sheet Conn-Rb-01
R250 = CMP-0018610-3: as R228 on sheet Conn-Rb-01
U27 = CMP-0073595-1: as U25 on sheet Conn-Rb-01

## Sheet Conn-TE-02.SchDoc
size A4; Date: Not shown in title block; ApprovedBy: Not shown in title block; CheckedBy: Not shown in title block; Author: Not shown in title block; CompanyName: Not shown in title block; Engineer: Not shown in title block; Organization: Not shown in title block; Address1: Not shown in title block; Address2: Not shown in title block; Address3: Not shown in title block; Address4: Not shown in title block; DocumentNumber: 9; Revision: Use project parameter SCH_Rev; SheetNumber: 9; SheetTotal: 15; PageSetup: Record=PageOptions¦CenterHorizontal=True¦CenterVertical=True¦PrintScale=1.00¦XCorrection=1.00¦YCorrection=1.00¦PrintKind=0¦BorderSize=5000000¦LeftOffset=0¦BottomOffset=0¦Orientation=2¦PaperLength=1000¦PaperWidth=1000¦Scale=100¦PaperSource=15¦PrintQuality=600¦MediaType=1¦DitherType=10¦PaperKind=Letter¦PrintScaleMode=1
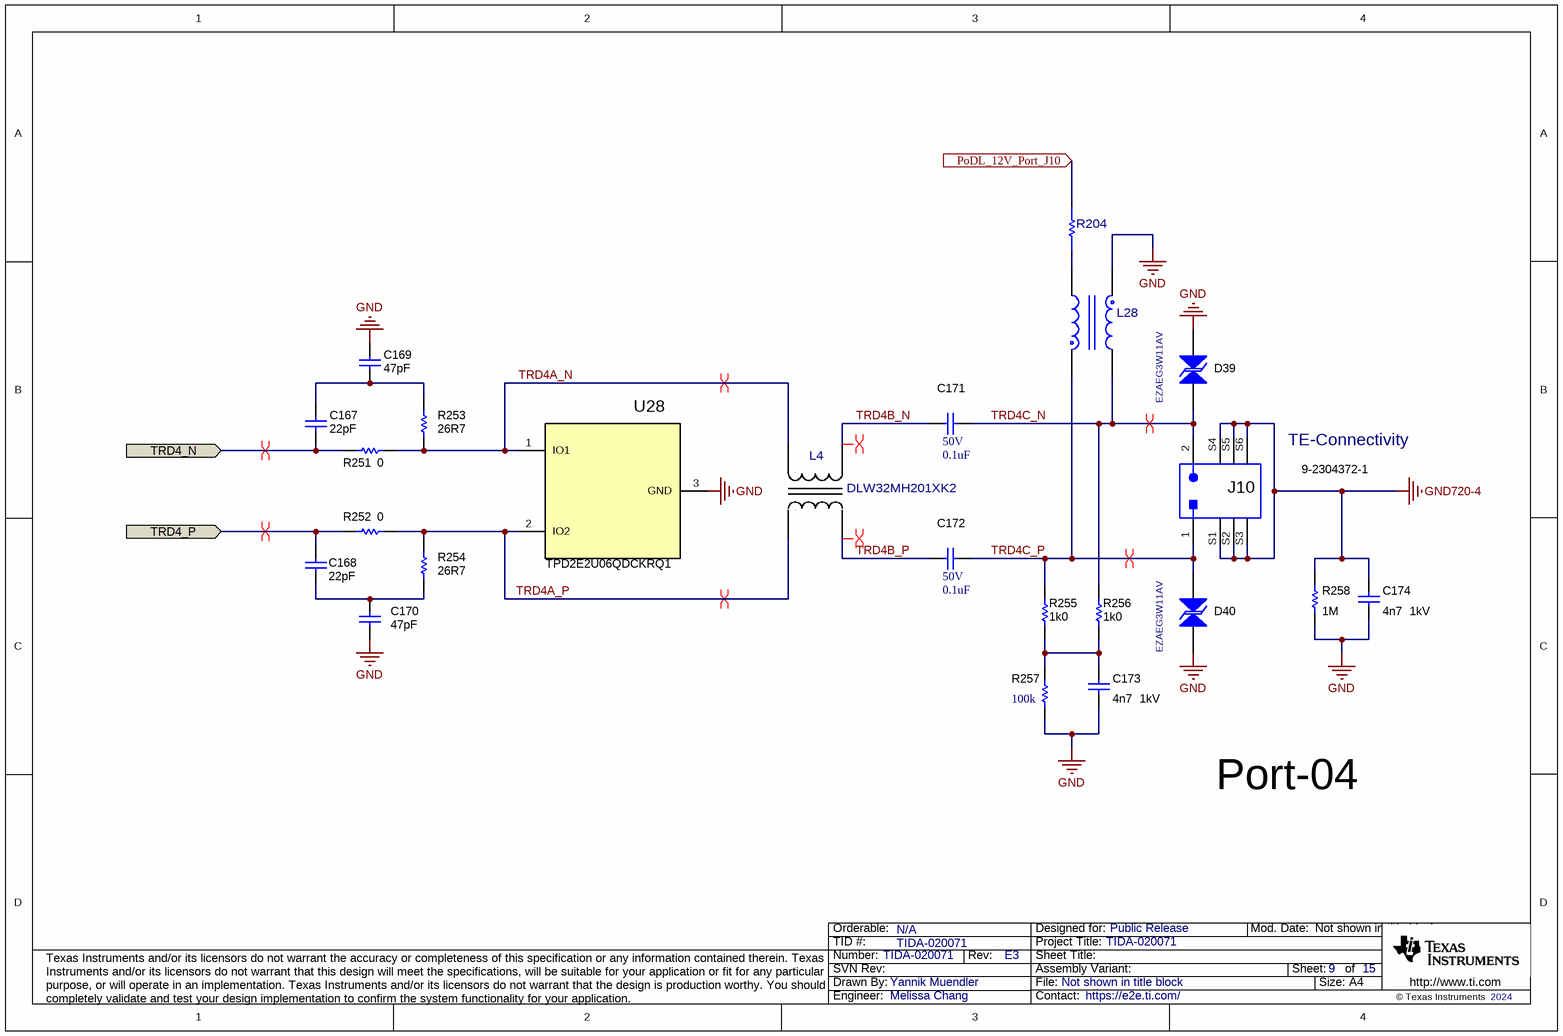
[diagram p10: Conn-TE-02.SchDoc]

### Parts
C167  ValueDisplayed: 22pF  [0402]  (hidden comment: GRM1555C1H220FA01D)
C168  ValueDisplayed: 22pF  [0402]  (hidden comment: GRM1555C1H220FA01D)
C169  ValueDisplayed: 47pF  [0402]  (hidden comment: GRM1555C1H470FA01D)
C170  ValueDisplayed: 47pF  [0402]  (hidden comment: GRM1555C1H470FA01D)
C171  VDC_V: 50V  ValueDisplayed: 0.1uF  [0402]  (hidden comment: GCM155R71H104KE02D)
C172  VDC_V: 50V  ValueDisplayed: 0.1uF  [0402]  (hidden comment: GCM155R71H104KE02D)
C173  VDC_V: 1kV  ValueDisplayed: 4n7  [1206]  (hidden comment: GRM31BR73A472KW01L)
C174  VDC_V: 1kV  ValueDisplayed: 4n7  [1206]  (hidden comment: GRM31BR73A472KW01L)
D39  EZAEG3W11AV  [0603]
D40  EZAEG3W11AV  [0603]
J10  9-2304372-1  Supplier 1: TE-Connectivity  [TE_1PORT_B1-B]
L4  DLW32MH201XK2  [FP-DLW32MH201XK2_1210-MFG]
L28  ADL32VHR-3R9M  [FP-ADL32VHR-3R9M_SMT_3MM2_2MM5-MFG]  (value not drawn)
R204  RMCF0805ZT0R00  [FP-RMCF0805ZT0R00_0805-MFG]  (value not drawn)
R251  ValueDisplayed: 0  [0402]  (hidden comment: CRCW04020000Z0EDHP)
R252  ValueDisplayed: 0  [0402]  (hidden comment: CRCW04020000Z0EDHP)
R253  ValueDisplayed: 26R7  [0402]  (hidden comment: CRCW040226R7FKED)
R254  ValueDisplayed: 26R7  [0402]  (hidden comment: CRCW040226R7FKED)
R255  ValueDisplayed: 1k0  [0805_HV]  (hidden comment: ERJ-P06F1001V)
R256  ValueDisplayed: 1k0  [0805_HV]  (hidden comment: ERJ-P06F1001V)
R257  ValueDisplayed: 100k  [0805_HV]  (hidden comment: CRCW0805100KFKEA)
R258  ValueDisplayed: 1M  [1206]  (hidden comment: CRCW12061M00JNEA)
U28  TPD2E2U06QDCKRQ1  [DCK0003A_N]

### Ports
PoDL_12V_Port_J10 (in), TRD4_N (in), TRD4_P (in)

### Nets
GND: C169.1 C170.2 C173.2 C174.2 D39.2 D40.1 L28.3 R257.1 R258.2 U28.3(GND)
GND720-4: C174.1 J10.S1(GND) J10.S2(GND) J10.S3(GND) J10.S4(GND) J10.S5(GND) J10.S6(GND) R258.1
PoDL_12V_Port_J10: R204.2 ; port PoDL_12V_Port_J10
TRD4_N: C167.2 R251.2 ; port TRD4_N
TRD4_P: C168.2 R252.2 ; port TRD4_P
TRD4A_N: L4.4 R251.1 R253.1 U28.1(IO1)
TRD4A_P: L4.1 R252.1 R254.1 U28.2(IO2)
TRD4B_N: C171.2 L4.3
TRD4B_P: C172.2 L4.2
TRD4C_N: C171.1 D39.1 J10.2 L28.4 R256.2
TRD4C_P: C172.1 D40.2 J10.1 L28.1 R255.2
NetC167_1: C167.1 C169.2 R253.2
NetC168_1: C168.1 C170.1 R254.2
NetC173_1: C173.1 R255.1 R256.1 R257.2
NetL28_2: L28.2 R204.1

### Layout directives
differential pair: TRD4_N, TRD4_P, TRD4A_N, TRD4A_P, TRD4B_N, TRD4B_P, TRD4C_N, TRD4C_P

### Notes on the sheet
- Port-04

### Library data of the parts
C167 C168 = CMP-0006438-2: as C137 on sheet Conn-Rb-01
C169 C170 = CMP-0006467-2: as C139 on sheet Conn-Rb-01
C171 C172 = CMP-0006356-2: as C141 on sheet Conn-Rb-01
C173 C174 = CMP-0008920-2: as C143 on sheet Conn-Rb-01
D39 D40 = CMP-0086344-1: as D33 on sheet Conn-Rb-01
J10 = CMP-0054903-1: as J7 on sheet Conn-Rb-01
L4 = CMP-0087001-1: as L3 on sheet Conn-TE-01
L28 = CMP-0098175-1: as L25 on sheet Conn-Rb-01
R204 = CMP-0089632-1: as R168 on sheet Conn-Rb-01
R251 R252 = CMP-0081856-1: as R1 on sheet Connector
R253 R254 = CMP-0026210-2: as R223 on sheet Conn-Rb-01
R255 R256 = CMP-0021848-2: as R225 on sheet Conn-Rb-01
R257 = CMP-0020834-3: as R227 on sheet Conn-Rb-01
R258 = CMP-0018610-3: as R228 on sheet Conn-Rb-01
U28 = CMP-0073595-1: as U25 on sheet Conn-Rb-01

## Sheet Hardware.SchDoc
size 431 x 279 mm; Date: Not shown in title block; ApprovedBy: Not shown in title block; CheckedBy: Not shown in title block; Author: Not shown in title block; CompanyName: Not shown in title block; Engineer: Not shown in title block; Organization: Not shown in title block; Address1: Not shown in title block; Address2: Not shown in title block; Address3: Not shown in title block; Address4: Not shown in title block; DocumentNumber: 15; Revision: Use project parameter SCH_Rev; SheetNumber: 15; SheetTotal: 15; PageSetup: Record=PageOptions¦CenterHorizontal=True¦CenterVertical=True¦PrintScale=1.00¦XCorrection=1.00¦YCorrection=1.00¦PrintKind=0¦BorderSize=5000000¦LeftOffset=0¦BottomOffset=0¦Orientation=2¦PaperLength=1000¦PaperWidth=1000¦Scale=100¦PaperSource=15¦PrintQuality=600¦MediaType=1¦DitherType=10¦PaperKind=Letter¦PrintScaleMode=1
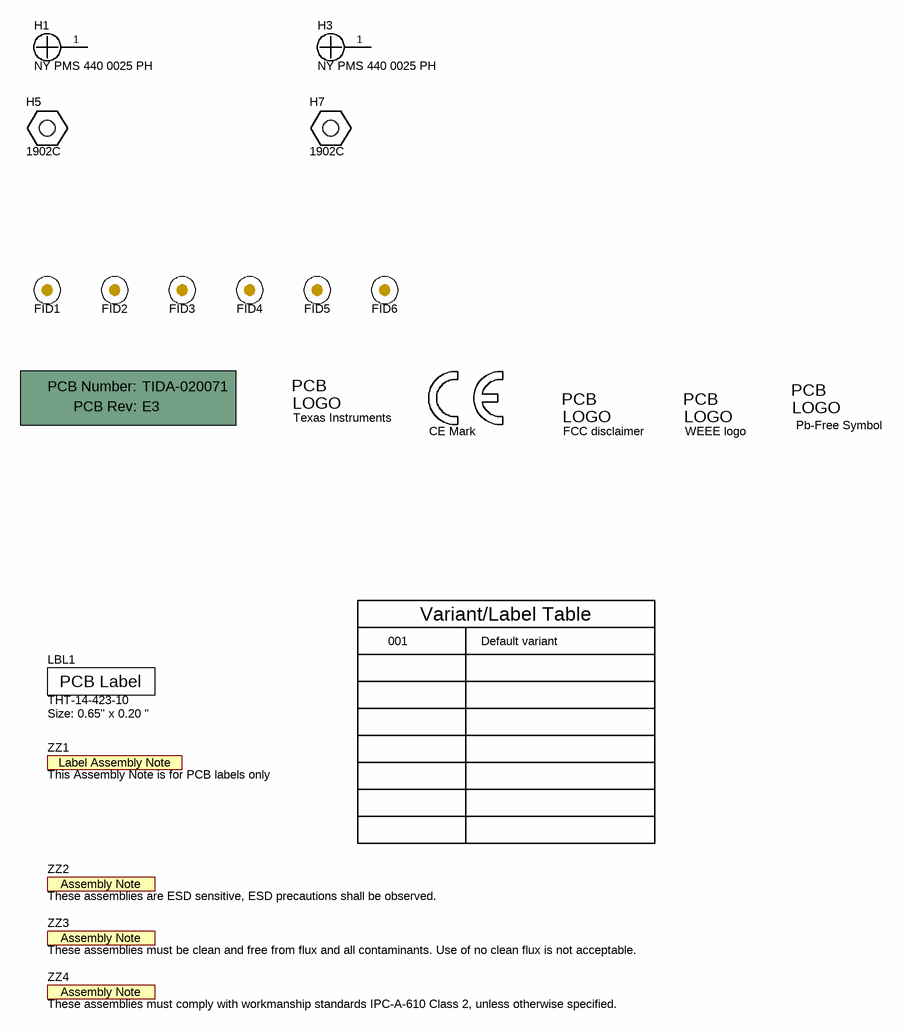
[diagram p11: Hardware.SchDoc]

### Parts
!PCB  Printed Circuit Board  (value not drawn)  (mechanical)
FID1  Fiducial  [Fiducial10-20]  (value not drawn)
FID2  Fiducial  [Fiducial10-20]  (value not drawn)
FID3  Fiducial  [Fiducial10-20]  (value not drawn)
FID4  Fiducial  [Fiducial10-20]  (value not drawn)
FID5  Fiducial  [Fiducial10-20]  (value not drawn)
FID6  Fiducial  [Fiducial10-20]  (value not drawn)
H1  NY PMS 440 0025 PH  [NY PMS 440 0025 PH]
H3  NY PMS 440 0025 PH  [NY PMS 440 0025 PH]
H5  1902C  [Keystone_1902C]
H7  1902C  [Keystone_1902C]
LBL1  THT-14-423-10  Note: Size: 0.65" x 0.20 "  [Label_650x200]
Logo1  Texas Instruments  [TI_Stacked_Overlay_Small]  (no BOM)
Logo2  CE Mark  [CE_Mark_5mm]  (no BOM)
Logo3  FCC disclaimer  [FCC_disclaimer]  (no BOM)
Logo4  WEEE logo  [WEEE_Minimum]  (no BOM)
Logo5  Pb-Free Symbol  [Pb-Free_Overlay_Small]  (no BOM)
ZZ1  This Assembly Note is for PCB labels only  [AssemblyNoteLabel]  (no BOM)
ZZ2  These assemblies are ESD sensitive, ESD precautions shall be observed.  [AssemblyNote]  (no BOM)
ZZ3  These assemblies must be clean and free from flux and all contaminants. Use of no clean flux is not acceptable.  [AssemblyNote]  (no BOM)
ZZ4  These assemblies must comply with workmanship standards IPC-A-610 Class 2, unless otherwise specified.  [AssemblyNote]  (no BOM)

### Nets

Not connected (* = marked no-connect by the designer): H1 1; H3 1

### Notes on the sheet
- 001
- Variant/Label Table
- Default variant

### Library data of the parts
!PCB = CMP-0003618-2: Manufacturer: Any; PartNumber: TIDA-020071
FID1-FID6 = CMP-0077181-1: Fiducial mark.  There is nothing to buy or mount.
H1 H3 = CMP-0003617-1: Machine Screw, Round, #4-40 x 1/4, Nylon, Philips panhead; Manufacturer: B&F Fastener Supply; CompType: Hardware
H5 H7 = CMP-0003610-1: Standoff, Hex, 0.5"L #4-40 Nylon; Manufacturer: Keystone; CompType: Hardware
LBL1 = CMP-0003625-1: Thermal Transfer Printable Labels, 0.650" W x 0.200" H - 10,000 per roll; Manufacturer: Brady; CompType: Label
Logo1 = CMP-0074838-1: Texas Instrument Corporate Signature; SymbolCreator: a0412235; Lib Reference: TI_Logo; Library Reference: Logo
Logo2 = CMP-0074844-1: SymbolCreator: a0412235
Logo3 = CMP-0074847-1: FCC_disclaimer; Library Reference: Logo
Logo4 = CMP-0074769-1
Logo5 = CMP-0074839-1: Library Reference: Logo; SymbolCreator: a0412235
ZZ1 = CMP-0003616-3
ZZ2 = CMP-0077236-1
ZZ3 = CMP-0077237-1
ZZ4 = CMP-0077238-1

## Sheet MDIO_MUX.SchDoc
size A3; Date: Not shown in title block; ApprovedBy: Not shown in title block; CheckedBy: Not shown in title block; Author: Not shown in title block; CompanyName: Not shown in title block; Engineer: Not shown in title block; Organization: Not shown in title block; Address1: Not shown in title block; Address2: Not shown in title block; Address3: Not shown in title block; Address4: Not shown in title block; DocumentNumber: 14; Revision: Use project parameter SCH_Rev; SheetNumber: 13; SheetTotal: 15; PageSetup: Record=PageOptions¦CenterHorizontal=True¦CenterVertical=True¦PrintScale=0.69¦XCorrection=1.00¦YCorrection=1.00¦PrintKind=0¦BorderSize=5000000¦LeftOffset=0¦BottomOffset=0¦Orientation=2¦PaperLength=1000¦PaperWidth=1000¦Scale=100¦PaperSource=15¦PrintQuality=600¦MediaType=1¦DitherType=10¦PaperKind=Letter¦PrintScaleMode=1
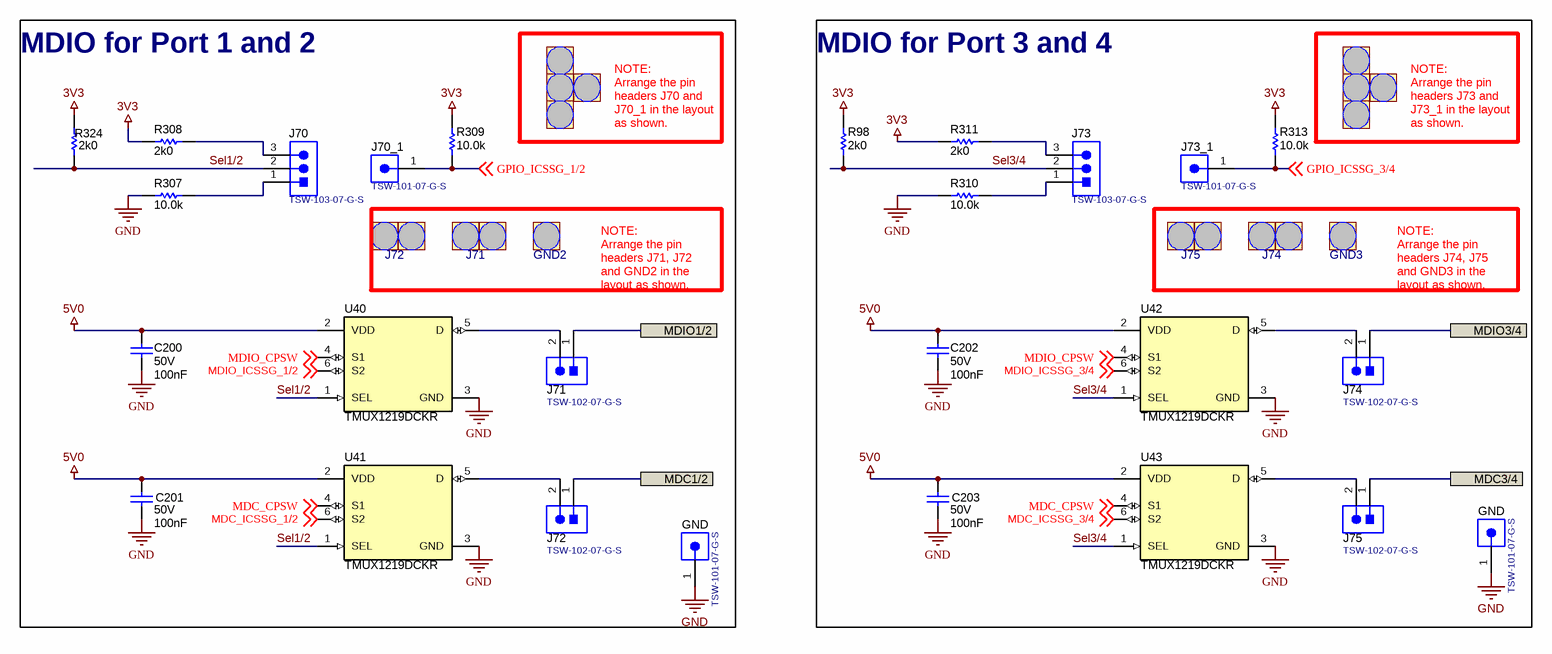
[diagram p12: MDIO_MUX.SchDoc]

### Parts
(Parts that share a designator on the sheet are numbered #1, #2 ... from top to bottom, then left to right.)
C200  VDC_V: 50V  ValueDisplayed: 100nF  [0402]  (hidden comment: C1005X5R1H104K050BB)
C201  VDC_V: 50V  ValueDisplayed: 100nF  [0402]  (hidden comment: C1005X5R1H104K050BB)
C202  VDC_V: 50V  ValueDisplayed: 100nF  [0402]  (hidden comment: C1005X5R1H104K050BB)
C203  VDC_V: 50V  ValueDisplayed: 100nF  [0402]  (hidden comment: C1005X5R1H104K050BB)
GND#5  TSW-101-07-G-S  [TSW-101-07-G-S]
GND#6  TSW-101-07-G-S  [TSW-101-07-G-S]
J70  TSW-103-07-G-S  [TSW-103-07-G-S]
J70_1  TSW-101-07-G-S  [TSW-101-07-G-S]
J71  TSW-102-07-G-S  [TSW-102-07-G-S]
J72  TSW-102-07-G-S  [TSW-102-07-G-S]
J73  TSW-103-07-G-S  [TSW-103-07-G-S]
J73_1  TSW-101-07-G-S  [TSW-101-07-G-S]
J74  TSW-102-07-G-S  [TSW-102-07-G-S]
J75  TSW-102-07-G-S  [TSW-102-07-G-S]
R98  ValueDisplayed: 2k0  [0402]  (hidden comment: RG1005P-202-B-T5)
R307  ValueDisplayed: 10.0k  [0402]  (hidden comment: CRCW040210K0FKED)
R308  ValueDisplayed: 2k0  [0402]  (hidden comment: RG1005P-202-B-T5)
R309  ValueDisplayed: 10.0k  [0402]  (hidden comment: CRCW040210K0FKED)
R310  ValueDisplayed: 10.0k  [0402]  (hidden comment: CRCW040210K0FKED)
R311  ValueDisplayed: 2k0  [0402]  (hidden comment: RG1005P-202-B-T5)
R313  ValueDisplayed: 10.0k  [0402]  (hidden comment: CRCW040210K0FKED)
R324  ValueDisplayed: 2k0  [0402]  (hidden comment: RG1005P-202-B-T5)
U40  TMUX1219DCKR  [DCK0006A_N]  (no BOM)
U41  TMUX1219DCKR  [DCK0006A_N]  (no BOM)
U42  TMUX1219DCKR  [DCK0006A_N]  (no BOM)
U43  TMUX1219DCKR  [DCK0006A_N]  (no BOM)

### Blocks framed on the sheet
MDIO for Port 1 and 2: C200 C201 GND#6 J70 J70_1 J71 J72 R307-R309 R324 U40 U41
MDIO for Port 3 and 4: C202 C203 GND#5 J73 J73_1 J74 J75 R98 R310 R311 R313 U42 U43

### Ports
MDC1/2, MDC3/4, MDIO1/2, MDIO3/4

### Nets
3V3: R98.1 R308.2 R309.1 R311.2 R313.1 R324.1
5V0: C200.2 C201.2 C202.2 C203.2 U40.2(VDD) U41.2(VDD) U42.2(VDD) U43.2(VDD)
GND: C200.1 C201.1 C202.1 C203.1 GND#5.1 GND#6.1 R307.2 R310.2 U40.3(GND) U41.3(GND) U42.3(GND) U43.3(GND)
GPIO_ICSSG_1/2: J70_1.1 R309.2 ; off-sheet GPIO_ICSSG_1/2
GPIO_ICSSG_3/4: J73_1.1 R313.2 ; off-sheet GPIO_ICSSG_3/4
MDC1/2: J72.1 ; port MDC1/2
MDC3/4: J75.1 ; port MDC3/4
MDC_CPSW: U41.4(S1) U43.4(S1) ; off-sheet MDC_CPSW
MDC_ICSSG_1/2: U41.6(S2) ; off-sheet MDC_ICSSG_1/2
MDC_ICSSG_3/4: U43.6(S2) ; off-sheet MDC_ICSSG_3/4
MDIO1/2: J71.1 ; port MDIO1/2
MDIO3/4: J74.1 ; port MDIO3/4
MDIO_CPSW: U40.4(S1) U42.4(S1) ; off-sheet MDIO_CPSW
MDIO_ICSSG_1/2: U40.6(S2) ; off-sheet MDIO_ICSSG_1/2
MDIO_ICSSG_3/4: U42.6(S2) ; off-sheet MDIO_ICSSG_3/4
Sel1/2: J70.2 R324.2 U40.1(SEL) U41.1(SEL)
Sel3/4: J73.2 R98.2 U42.1(SEL) U43.1(SEL)
NetJ70_1: J70.1 R307.1
NetJ70_3: J70.3 R308.1
NetJ71_2: J71.2 U40.5(D)
NetJ72_2: J72.2 U41.5(D)
NetJ73_1: J73.1 R310.1
NetJ73_3: J73.3 R311.1
NetJ74_2: J74.2 U42.5(D)
NetJ75_2: J75.2 U43.5(D)

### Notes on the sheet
- NOTE:
  Arrange the pin headers J70 and J70_1 in the layout as shown.
- NOTE:
  Arrange the pin headers J73 and J73_1 in the layout as shown.
- J72
- J71
- GND2
- NOTE:
  Arrange the pin headers J71, J72 and GND2 in the layout as shown.
- J75
- J74
- GND3
- NOTE:
  Arrange the pin headers J74, J75 and GND3 in the layout as shown.

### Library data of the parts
C200-C203 = CMP-0006279-2: CAP, CERM, 0.1 uF, 50 V, +/- 10%, X5R, 0402; Manufacturer: TDK; TaMin_C: -55°C; ESR_ohm: 39.064m; Polarized: N; SizeAreaWB_mm2: 3; Value1: 0.039064 ohm; U/M: EA; Value: 0.1uF; TaMax_C: 85°C; SizeZ_mm: 0.6; SizeX_mm: 1; SizeY_mm: 0.5; IRMS_A: 814.669mA; AEC Category: Q200
GND#5 GND#6 J70_1 J73_1 = CMP-0075403-1: as 1V8 on sheet Connector
J70 J73 = CMP-0075407-2: as J35_PTP_PHY_1 on sheet Connector
J71 J72 J74 J75 = CMP-0075405-3: as J37 on sheet Connector
R98 R308 R311 R324 = CMP-0026816-1: RES, 2.00 k, 0.1%, 0.063 W, 0402; Manufacturer: Susumu Co Ltd; Power_W: 63mW; TempCo: 25 ppm/C; Value_Code: 2k00; U/M: EA; Value: 2.00k; EIA_Code: E192; Res_ohm: 2k; SizeX_mm: 1; SizeY_mm: 0.5; SizeZ_mm: 0.6; Value2: 0.063W; AEC Category: Q200
R307 R309 R310 R313 = CMP-0025958-1: RES, 10.0 k, 1%, 0.063 W, 0402; Manufacturer: Vishay-Dale; Power_W: 63mW; TempCo: 100 ppm/C; Value_Code: 10k0; U/M: EA; Value: 10.0k; EIA_Code: E96; Res_ohm: 10k; SizeX_mm: 1; SizeY_mm: 0.5; SizeZ_mm: 0.6; Value2: 0.063W; VDC_V: 50V; AEC Category: Q200
U40-U43 = CMP-0860319-1: 1-ch, 2:1 general-purpose analog multiplexer with 1.8-V logic control, DCK0006A (SOT-SC70-6); Alternate Manufacturer: Texas Instruments; SizeY_mm: 2; SizeArea_mm2: 4.2; SizeX_mm: 2.1; AEC Category: Q200; Rating: Catalog; CompType: IC; SizeZ_mm: 1.1; SizeAreaWB_mm2: 9.3; AEC Qualified: N

## Sheet HSS and Memory.SchDoc
size A4; Date: Not shown in title block; ApprovedBy: Not shown in title block; CheckedBy: Not shown in title block; Author: Not shown in title block; CompanyName: Not shown in title block; Engineer: Not shown in title block; Organization: Not shown in title block; Address1: Not shown in title block; Address2: Not shown in title block; Address3: Not shown in title block; Address4: Not shown in title block; DocumentNumber: 15; Revision: Use project parameter SCH_Rev; SheetNumber: 15; SheetTotal: 15; PageSetup: Record=PageOptions¦CenterHorizontal=True¦CenterVertical=True¦PrintScale=1.00¦XCorrection=1.00¦YCorrection=1.00¦PrintKind=0¦BorderSize=5000000¦LeftOffset=0¦BottomOffset=0¦Orientation=2¦PaperLength=1000¦PaperWidth=1000¦Scale=100¦PaperSource=15¦PrintQuality=600¦MediaType=1¦DitherType=10¦PaperKind=Letter¦PrintScaleMode=1
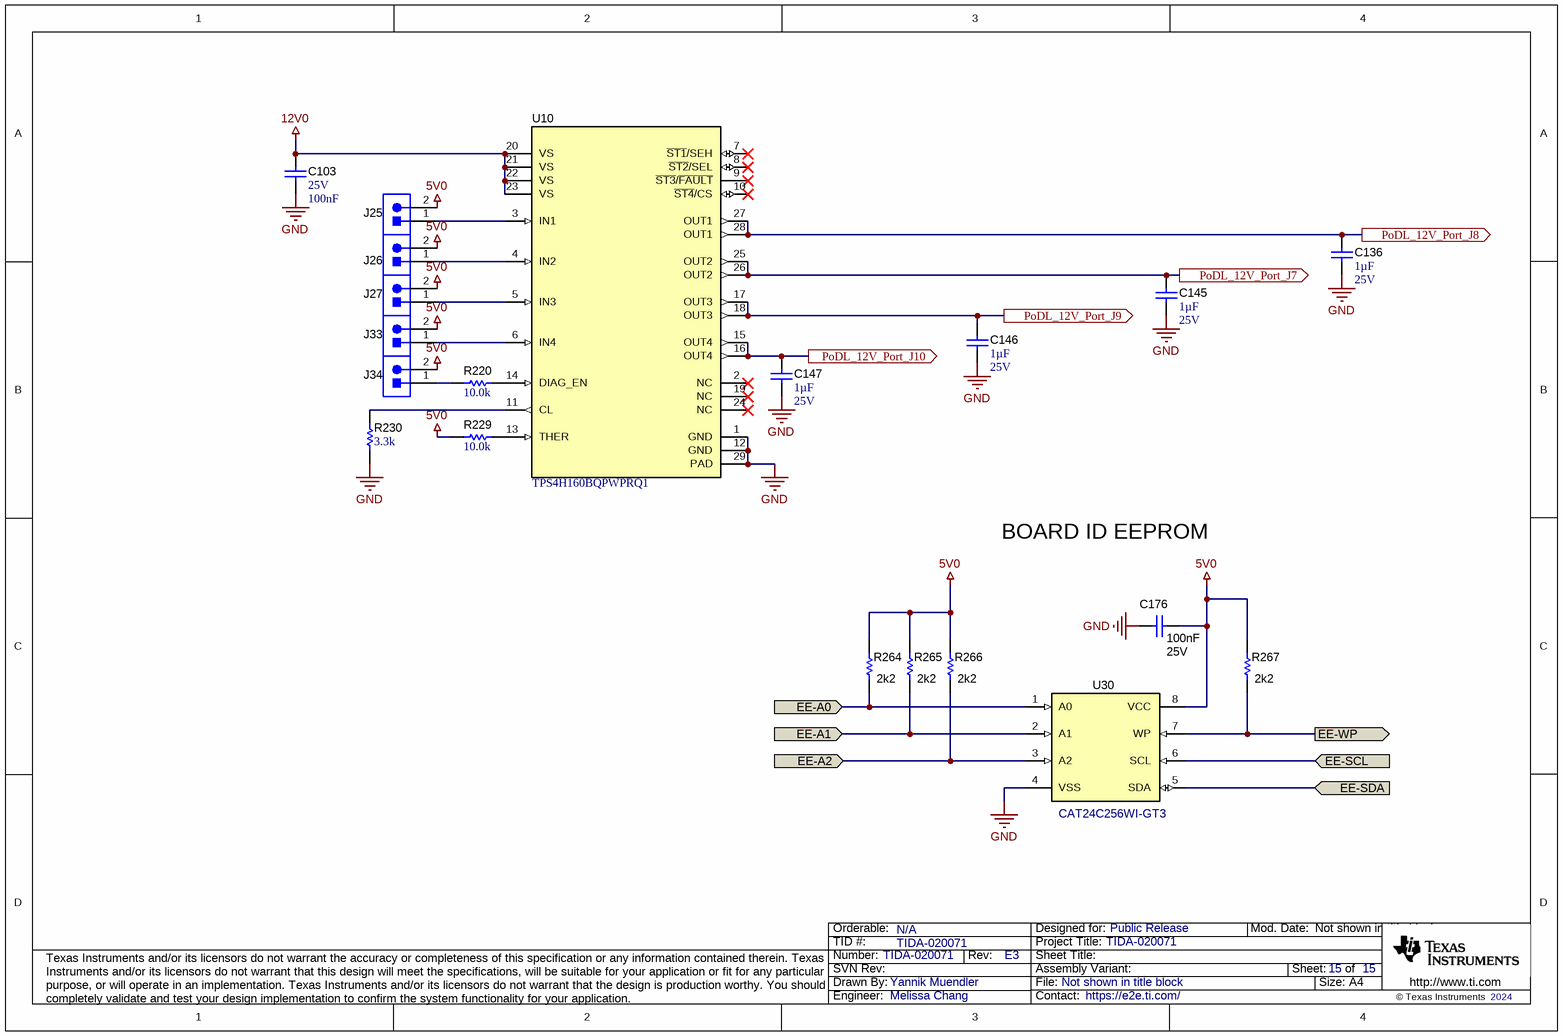
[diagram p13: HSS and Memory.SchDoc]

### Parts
C103  VDC_V: 25V  Cap_F: 100nF  [0603]  (hidden comment: GCM188R71E104KA57D)
C136  Cap_F: 1µF  VDC_V: 25V  [0603]  (hidden comment: CGA3E1X7R1E105K080AD)
C145  Cap_F: 1µF  VDC_V: 25V  [0603]  (hidden comment: CGA3E1X7R1E105K080AD)
C146  Cap_F: 1µF  VDC_V: 25V  [0603]  (hidden comment: CGA3E1X7R1E105K080AD)
C147  Cap_F: 1µF  VDC_V: 25V  [0603]  (hidden comment: CGA3E1X7R1E105K080AD)
C176  VDC_V: 25V  ValueDisplayed: 100nF  [0402]  (hidden comment: GRM155R61E105KA12D)
J25  TSW-102-07-G-S  [TSW-102-07-G-S]  (value not drawn)
J26  TSW-102-07-G-S  [TSW-102-07-G-S]  (value not drawn)
J27  TSW-102-07-G-S  [TSW-102-07-G-S]  (value not drawn)
J33  TSW-102-07-G-S  [TSW-102-07-G-S]  (value not drawn)
J34  TSW-102-07-G-S  [TSW-102-07-G-S]  (value not drawn)
R220  ValueDisplayed: 10.0k  [0603]  (hidden comment: CRCW060310K0FKEA)
R229  ValueDisplayed: 10.0k  [0603]  (hidden comment: CRCW060310K0FKEA)
R230  ValueDisplayed: 3.3k  [0603]  (hidden comment: CRCW06033K30JNEA)
R264  ValueDisplayed: 2k2  [0402]  (hidden comment: CRCW04022K20JNED)
R265  ValueDisplayed: 2k2  [0402]  (hidden comment: CRCW04022K20JNED)
R266  ValueDisplayed: 2k2  [0402]  (hidden comment: CRCW04022K20JNED)
R267  ValueDisplayed: 2k2  [0402]  (hidden comment: CRCW04022K20JNED)
U10  TPS4H160BQPWPRQ1  [PWP0028C_N]
U30  CAT24C256WI-GT3  [SOIC-8]

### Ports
EE-A0 (in), EE-A1 (in), EE-A2 (in), EE-SCL (in), EE-SDA (in), EE-WP (out), PoDL_12V_Port_J7 (out), PoDL_12V_Port_J8 (out), PoDL_12V_Port_J9 (out), PoDL_12V_Port_J10 (out)

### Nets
5V0: C176.2 J25.2 J26.2 J27.2 J33.2 J34.2 R229.1 R264.2 R265.2 R266.2 R267.2 U30.8(VCC)
12V0: C103.1 U10.20(VS) U10.21(VS) U10.22(VS) U10.23(VS)
GND: C103.2 C136.2 C145.2 C146.2 C147.2 C176.1 R230.1 U10.1(GND) U10.12(GND) U10.29(PAD) U30.4(VSS)
EE-A0: R264.1 U30.1(A0) ; port EE-A0
EE-A1: R265.1 U30.2(A1) ; port EE-A1
EE-A2: R266.1 U30.3(A2) ; port EE-A2
EE-SCL: U30.6(SCL) ; port EE-SCL
EE-SDA: U30.5(SDA) ; port EE-SDA
EE-WP: R267.1 U30.7(WP) ; port EE-WP
PoDL_12V_Port_J7: C145.1 U10.25(OUT2) U10.26(OUT2) ; port PoDL_12V_Port_J7
PoDL_12V_Port_J8: C136.1 U10.27(OUT1) U10.28(OUT1) ; port PoDL_12V_Port_J8
PoDL_12V_Port_J9: C146.1 U10.17(OUT3) U10.18(OUT3) ; port PoDL_12V_Port_J9
PoDL_12V_Port_J10: C147.1 U10.15(OUT4) U10.16(OUT4) ; port PoDL_12V_Port_J10
NetJ25_1: J25.1 U10.3(IN1)
NetJ26_1: J26.1 U10.4(IN2)
NetJ27_1: J27.1 U10.5(IN3)
NetJ33_1: J33.1 U10.6(IN4)
NetJ34_1: J34.1 R220.1
NetR220_2: R220.2 U10.14(DIAG_EN)
NetR229_2: R229.2 U10.13(THER)
NetR230_2: R230.2 U10.11(CL)

Not connected (* = marked no-connect by the designer): U10 2(NC)* 7(~{ST1}/SEH)* 8(~{ST2}/SEL)* 9(~{ST3}/~{FAULT})* 10(~{ST4}/CS)* 19(NC)* 24(NC)*

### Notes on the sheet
- BOARD ID EEPROM

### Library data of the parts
C103 = CMP-0084679-1: CAP, CERM, 0.1 µF, 25 V,+/- 10%, X7R, AEC-Q200 Grade 1, 0603; Manufacturer: MuRata; TaMin_C: -55°C; SizeY_mm: 0.8; Polarized: N; SizeArea_mm2: 1.28; SizeZ_mm: 1; SizeX_mm: 1.6; AEC Qualified: Y; AEC Category: Q200; Value: 0.1uF; ValueDisplayed: 0.1µF; TaMax_C: 125°C; U/M: EA; SizeAreaWB_mm2: 4.68
C136 C145-C147 = CMP-0082523-1: CAP, CERM, 1 µF, 25 V,+/- 10%, X7R, AEC-Q200 Grade 1, 0603; Manufacturer: TDK; SizeAreaWB_mm2: 4.68; SizeArea_mm2: 1.28; AEC Qualified: Y; AEC Category: Q200; Value: 1uF; TaMax_C: 125°C; SizeZ_mm: 1; Polarized: N; TaMin_C: -55°C; SizeY_mm: 0.8; U/M: EA; SizeX_mm: 1.6
C176 = CMP-0006608-2: CAP, CERM, 1 uF, 25 V, +/- 10%, X5R, 0402; Manufacturer: MuRata; TaMin_C: -55°C; Polarized: N; SizeAreaWB_mm2: 3; Value1: Unknown; U/M: EA; Value: 1uF; TaMax_C: 85°C; SizeZ_mm: 0.6; SizeX_mm: 1; SizeY_mm: 0.5; Cap_F: 1µF; AEC Category: Q200
J25-J27 J33 J34 = CMP-0075405-3: Header, 100mil, 2x1, Gold, TH; Manufacturer: Samtec; Current_A: 6.3A; Green_Lifecycle: Active; Pitch_mm: 2.54; Cert_CSA: Y; Cert_VDE: N; Green_REACh: Passed; Row_Count: 1; Gender: Male; Voltage_V: 550V
R220 R229 = CMP-0021998-4: RES, 10.0 k, 1%, 0.1 W, AEC-Q200 Grade 0, 0603; Manufacturer: Vishay-Dale; Power_W: 100mW; TempCo: 100 ppm/C; Value_Code: 10k0; Value: 10.0k; EIA_Code: E96; Res_ohm: 10k; SizeX_mm: 1.6; SizeY_mm: 0.8; SizeZ_mm: 1; Value2: 0.1W; SizeArea_mm2: 1.28; AEC Qualified: Y; VDC_V: 75V; AEC Category: Q200; AEC Grade: 0
R230 = CMP-0025797-4: RES, 3.3 k, 5%, 0.1 W, AEC-Q200 Grade 0, 0603; Manufacturer: Vishay-Dale; Power_W: 100mW; TempCo: 200 ppm/C; Value_Code: 3k30; Value: 3.3k; EIA_Code: E24; SizeX_mm: 1.6; SizeY_mm: 0.8; SizeZ_mm: 1; Value2: 0.1W; SizeArea_mm2: 1.28; AEC Qualified: Y; VDC_V: 75V; AEC Category: Q200; AEC Grade: 0
R264-R267 = CMP-0026890-5: as R268 on sheet Connector
U10 = CMP-0073696-3: 40-V/160-mohm Quad Channels Smart High-Side Switch, PWP0028C (TSSOP-28); Manufacturer: Texas Instruments; SizeX_mm: 6.4; SizeY_mm: 9.7; CompType: IC; SizeZ_mm: 1.2; SizeArea_mm2: 62.08; SizeAreaWB_mm2: 98.28; Green_Lifecycle: Active; Green_REACh: Passed; AEC Category: Q200; AEC Qualified: Y
U30 = CMP-0005313-2: 256 kb I2C CMOS Serial EEPROM, SOIC-8; Manufacturer: ON Semiconductor; SizeArea_mm2: 29.351; SizeAreaWB_mm2: 55.131; SizeX_mm: 5.99; SizeY_mm: 4.9; SizeZ_mm: 1.75

## Sheet Reset.SchDoc
size A4; Date: Not shown in title block; ApprovedBy: Not shown in title block; CheckedBy: Not shown in title block; Author: Not shown in title block; CompanyName: Not shown in title block; Engineer: Not shown in title block; Organization: Not shown in title block; Address1: Not shown in title block; Address2: Not shown in title block; Address3: Not shown in title block; Address4: Not shown in title block; DocumentNumber: 12; Revision: Use project parameter SCH_Rev; SheetNumber: 12; SheetTotal: 15; PageSetup: Record=PageOptions¦CenterHorizontal=True¦CenterVertical=True¦PrintScale=1.00¦XCorrection=1.00¦YCorrection=1.00¦PrintKind=0¦BorderSize=5000000¦LeftOffset=0¦BottomOffset=0¦Orientation=2¦PaperLength=1000¦PaperWidth=1000¦Scale=100¦PaperSource=15¦PrintQuality=600¦MediaType=1¦DitherType=10¦PaperKind=Letter¦PrintScaleMode=1
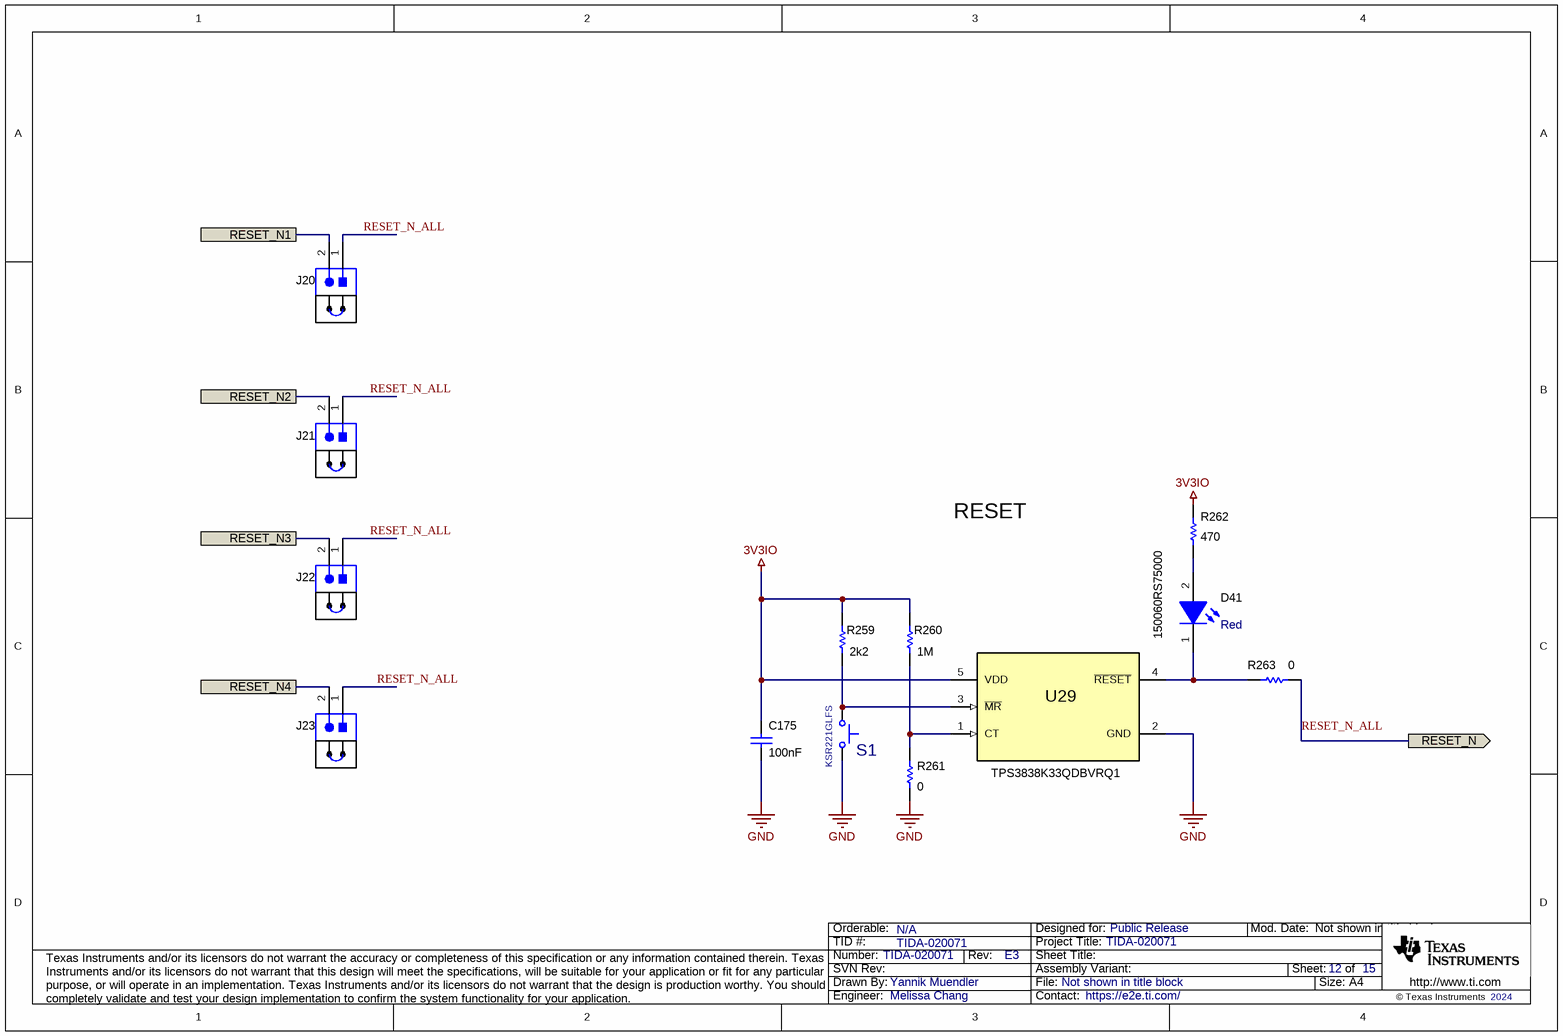
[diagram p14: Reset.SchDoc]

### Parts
C175  ValueDisplayed: 100nF  [0402]  (hidden comment: C1005X5R1H104K050BB)
D41  150060RS75000  value Red  [WL-SMCW_RED]
J20  TSW-102-07-G-S  [TSW-102-07-G-S]  (value not drawn)
J21  TSW-102-07-G-S  [TSW-102-07-G-S]  (value not drawn)
J22  TSW-102-07-G-S  [TSW-102-07-G-S]  (value not drawn)
J23  TSW-102-07-G-S  [TSW-102-07-G-S]  (value not drawn)
R259  ValueDisplayed: 2k2  [0402]  (hidden comment: ERA2AEB222X)
R260  ValueDisplayed: 1M  [0402]  (hidden comment: ERJ-2RKF1004X)
R261  ValueDisplayed: 0  [0402]  (hidden comment: CRCW04020000Z0EDHP)
R262  ValueDisplayed: 470  [0402]  (hidden comment: RC0402FR-07470RL)
R263  ValueDisplayed: 0  [0402]  (hidden comment: CRCW04020000Z0EDHP)
S1  KSR221GLFS  [KSR]
SH-J13  881545-2  [TE_881545-2]  (value not drawn)  (mechanical)
SH-J14  881545-2  [TE_881545-2]  (value not drawn)  (mechanical)
SH-J15  881545-2  [TE_881545-2]  (value not drawn)  (mechanical)
SH-J16  881545-2  [TE_881545-2]  (value not drawn)  (mechanical)
U29  TPS3838K33QDBVRQ1  [DBV0005A_N]

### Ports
RESET_N1, RESET_N2, RESET_N3, RESET_N4, RESET_N (out)

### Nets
3V3IO: C175.1 R259.2 R260.1 R262.2 U29.5(VDD)
GND: C175.2 R261.1 S1.2 U29.2(GND)
RESET_N1: J20.2 ; port RESET_N1
RESET_N2: J21.2 ; port RESET_N2
RESET_N3: J22.2 ; port RESET_N3
RESET_N4: J23.2 ; port RESET_N4
RESET_N_ALL: J20.1 J21.1 J22.1 J23.1 R263.2 ; port RESET_N
NetD41_1: D41.1(K) R263.1 U29.4(~{RESET})
NetD41_2: D41.2(A) R262.1
NetR259_1: R259.1 S1.1 U29.3(~{MR})
NetR260_2: R260.2 R261.2 U29.1(CT)

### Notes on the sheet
- RESET

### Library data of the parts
C175 = CMP-0006279-2: CAP, CERM, 0.1 uF, 50 V, +/- 10%, X5R, 0402; Manufacturer: TDK; TaMin_C: -55°C; ESR_ohm: 0.039064; Polarized: N; SizeAreaWB_mm2: 3; Value1: 0.039064 ohm; U/M: EA; Value: 0.1uF; TaMax_C: 85°C; SizeZ_mm: 0.6; SizeX_mm: 1; SizeY_mm: 0.5; Value2: 50V; IRMS_A: 814.669mA; AEC Category: Q200
D41 = CMP-0002947-3: LED, Red, SMD; Manufacturer: Wurth Elektronik; Value1: 0.072W; Vf_V: 2V; Angle: 140; Tjmax_C: 85°C; Type: AlInGaP; Vr_V: 5V; Io_A: 30mA; Power_TotalModule: 72mW
J20-J23 = CMP-0075405-3: as J37 on sheet Connector
R259 = CMP-0074667-1: RES, 2.20 k, 0.1%, 0.0625 W, AEC-Q200 Grade 0, 0402; Manufacturer: Panasonic; Power_W: 62.5mW; TempCo: 25 ppm/C; Value_Code: 2k20; U/M: EA; Value: 2.20k; Res_ohm: 2.2k; SizeX_mm: 1.0; SizeY_mm: 0.5; SizeZ_mm: 0.6; AEC Qualified: Y; VDC_V: 50V; AEC Grade: 0; AEC Category: Q200
R260 = CMP-0026660-1: RES, 1.00 M, 1%, 0.1 W, 0402; Manufacturer: Panasonic; Power_W: 100mW; TempCo: 100 ppm/C; Value_Code: 1M00; U/M: EA; Value: 1.00Meg; EIA_Code: E96; SizeX_mm: 1; SizeY_mm: 0.5; SizeZ_mm: 0.6; Value2: 0.1W; VDC_V: 50V; AEC Category: Q200
R261 R263 = CMP-0081856-1: as R1 on sheet Connector
R262 = CMP-0026736-1: RES, 470, 1%, 0.063 W, 0402; Manufacturer: Yageo America; Power_W: 63mW; TempCo: 100 ppm/C; Value_Code: 470R; U/M: EA; Value: 470; SizeX_mm: 1; SizeY_mm: 0.5; SizeZ_mm: 0.6; Value2: 0.063W; AEC Qualified: N; VDC_V: 50V; AEC Category: Q200
S1 = CMP-0002170-2: Switch, Normally open, 2.3N force, 200k operations, SMD; Manufacturer: C&K Components; CurrentRating_mA: 1.001kA; SwitchFunction: Off-Mom; Circuit: SPST Switch; VDC_V: 32V; PositionCount: 1
SH-J13-SH-J16 = 881545-2: Shunt, 100mil, Gold plated, Black; Manufacturer: TE Connectivity
U29 = CMP-0074267-1: Nanopower Supervisory Circuits for Automotive, DBV0005A (SOT-23-5); Alternate Manufacturer: Texas Instruments; SizeAreaWB_mm2: 14.82; U/M: EA; SizeZ_mm: 1.45; SizeX_mm: 2.8; SizeY_mm: 2.9; SizeArea_mm2: 8.12; CompType: IC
